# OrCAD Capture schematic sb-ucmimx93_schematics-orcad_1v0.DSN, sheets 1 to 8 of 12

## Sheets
1 01 Index and Block Diagram: title: SB-UCMIMX93   01. INDEX AND BLOCK DIAGRAM; rev: 1.0; note: 8000215000
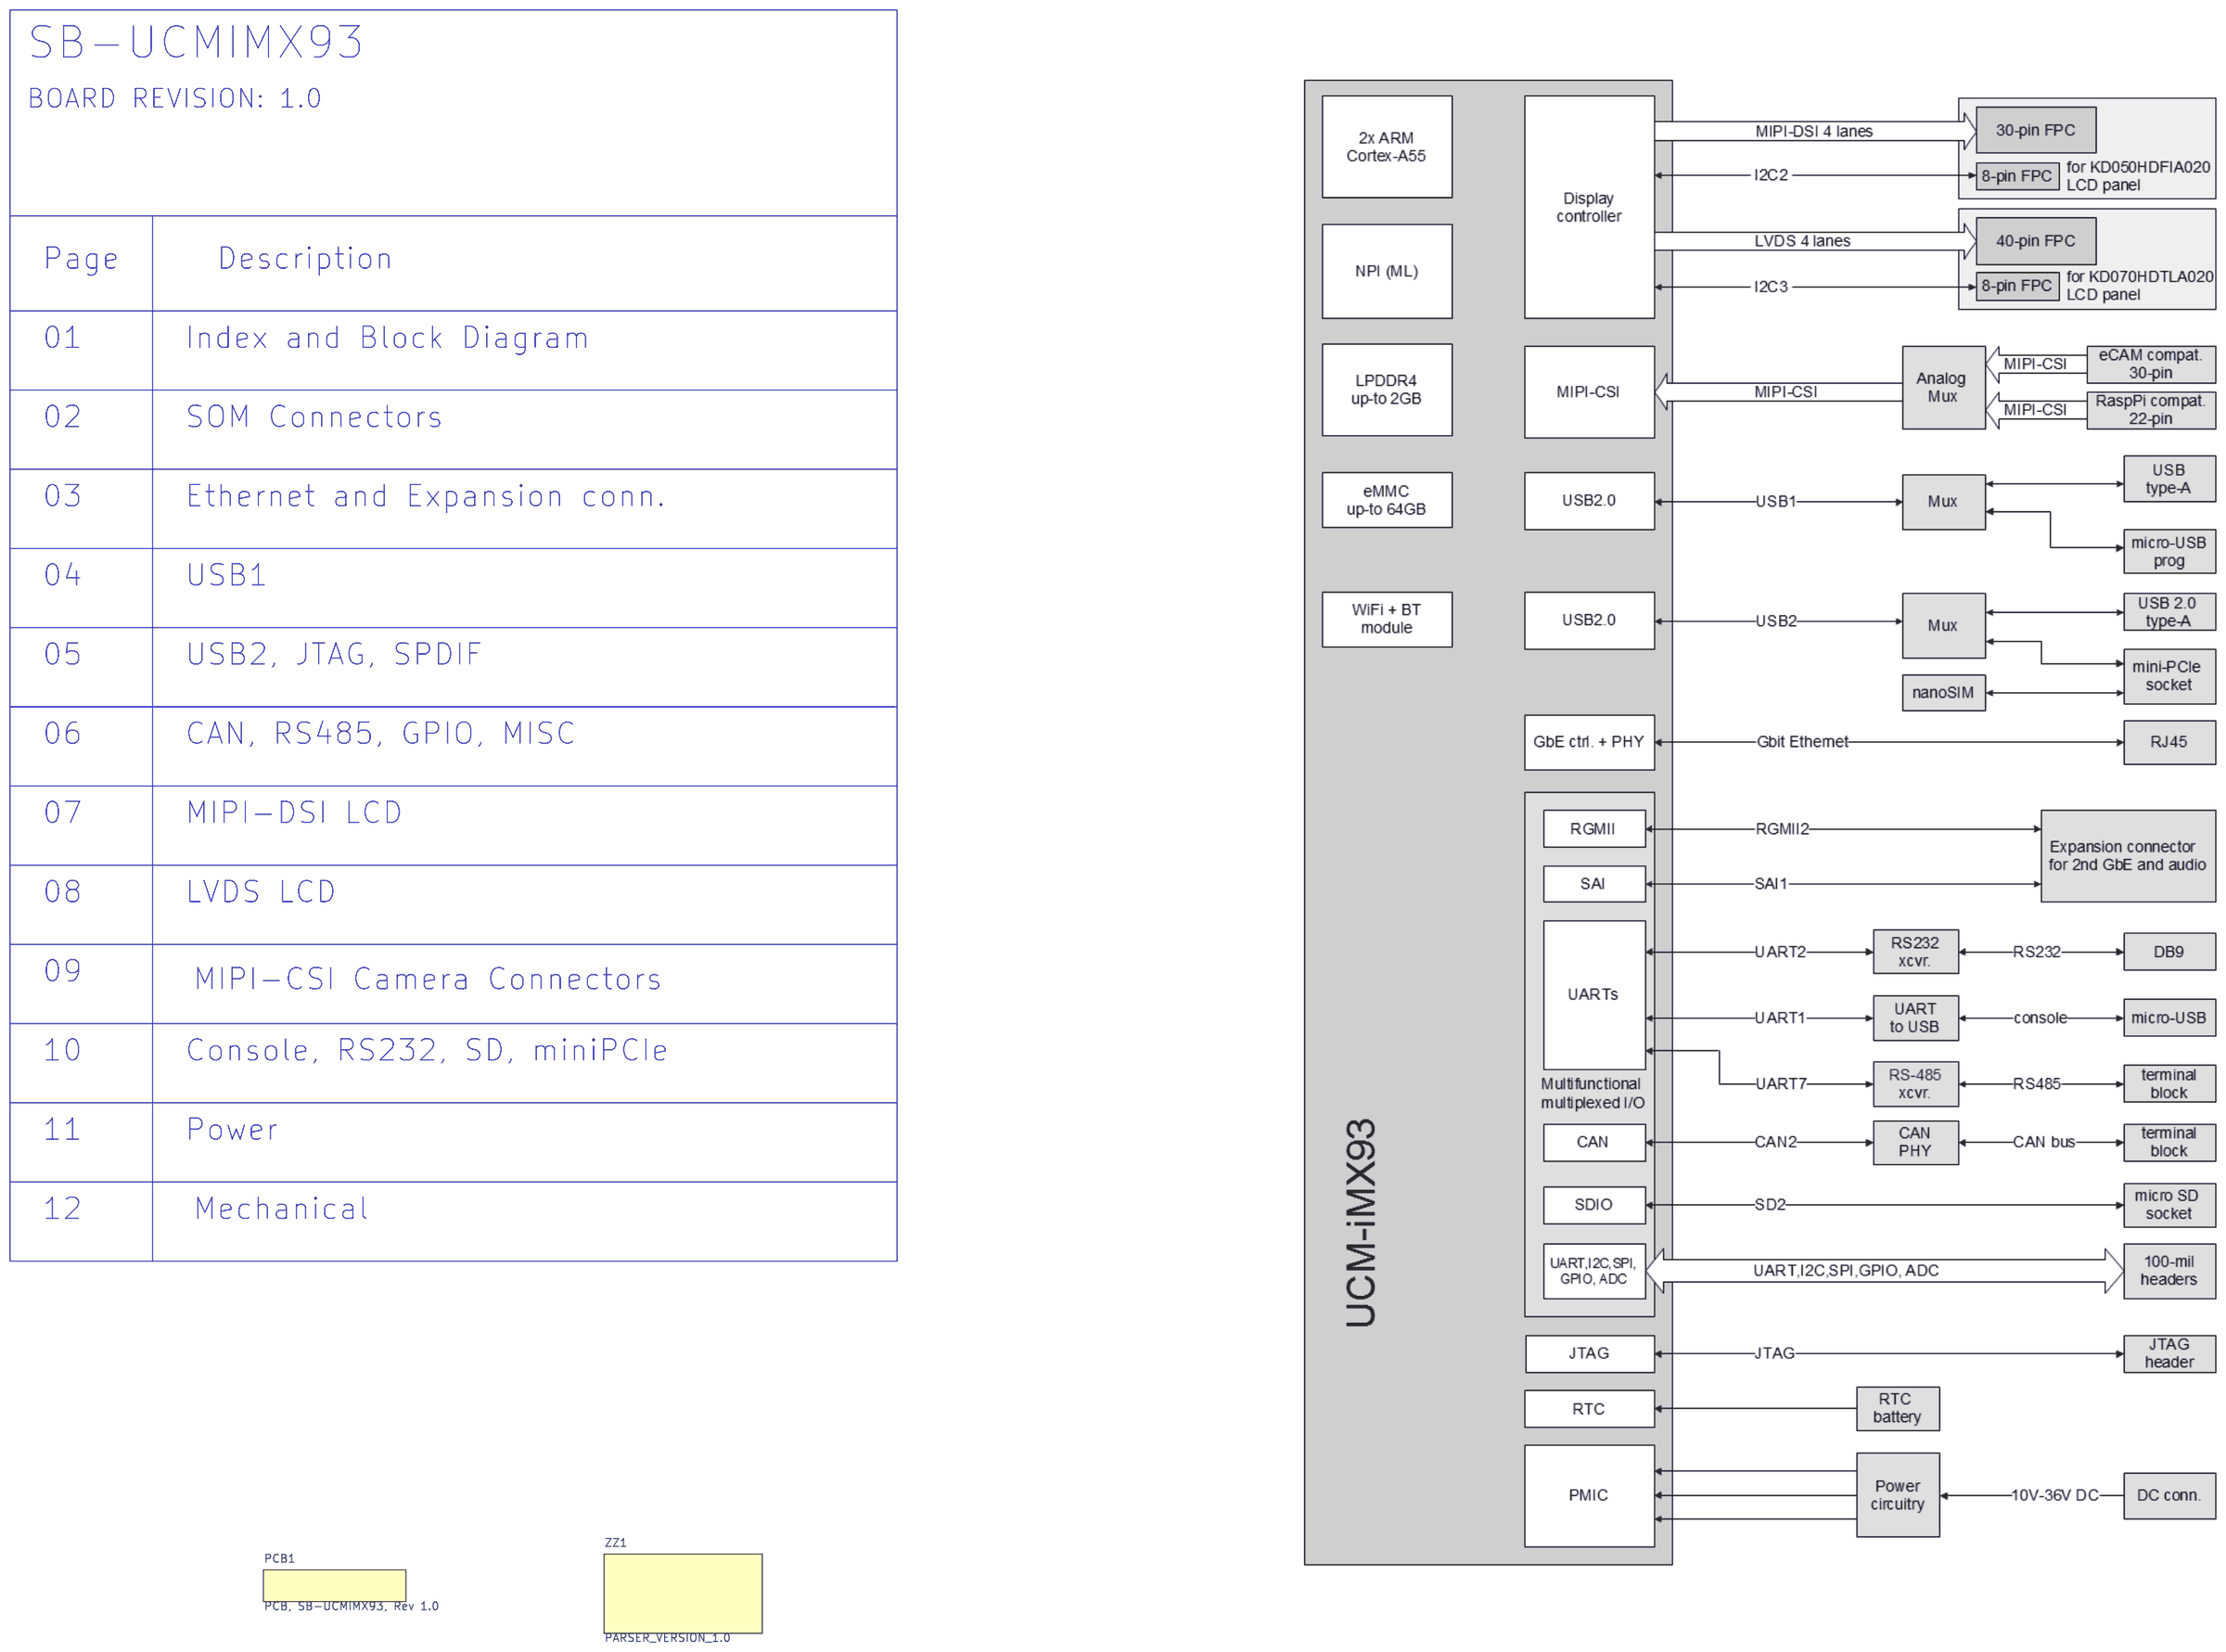
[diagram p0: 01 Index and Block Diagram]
2 05 USB2, JTAG, SPDIF: size A3; title: SB-UCMIMX93      05. USB2, JTAG, SPDIF
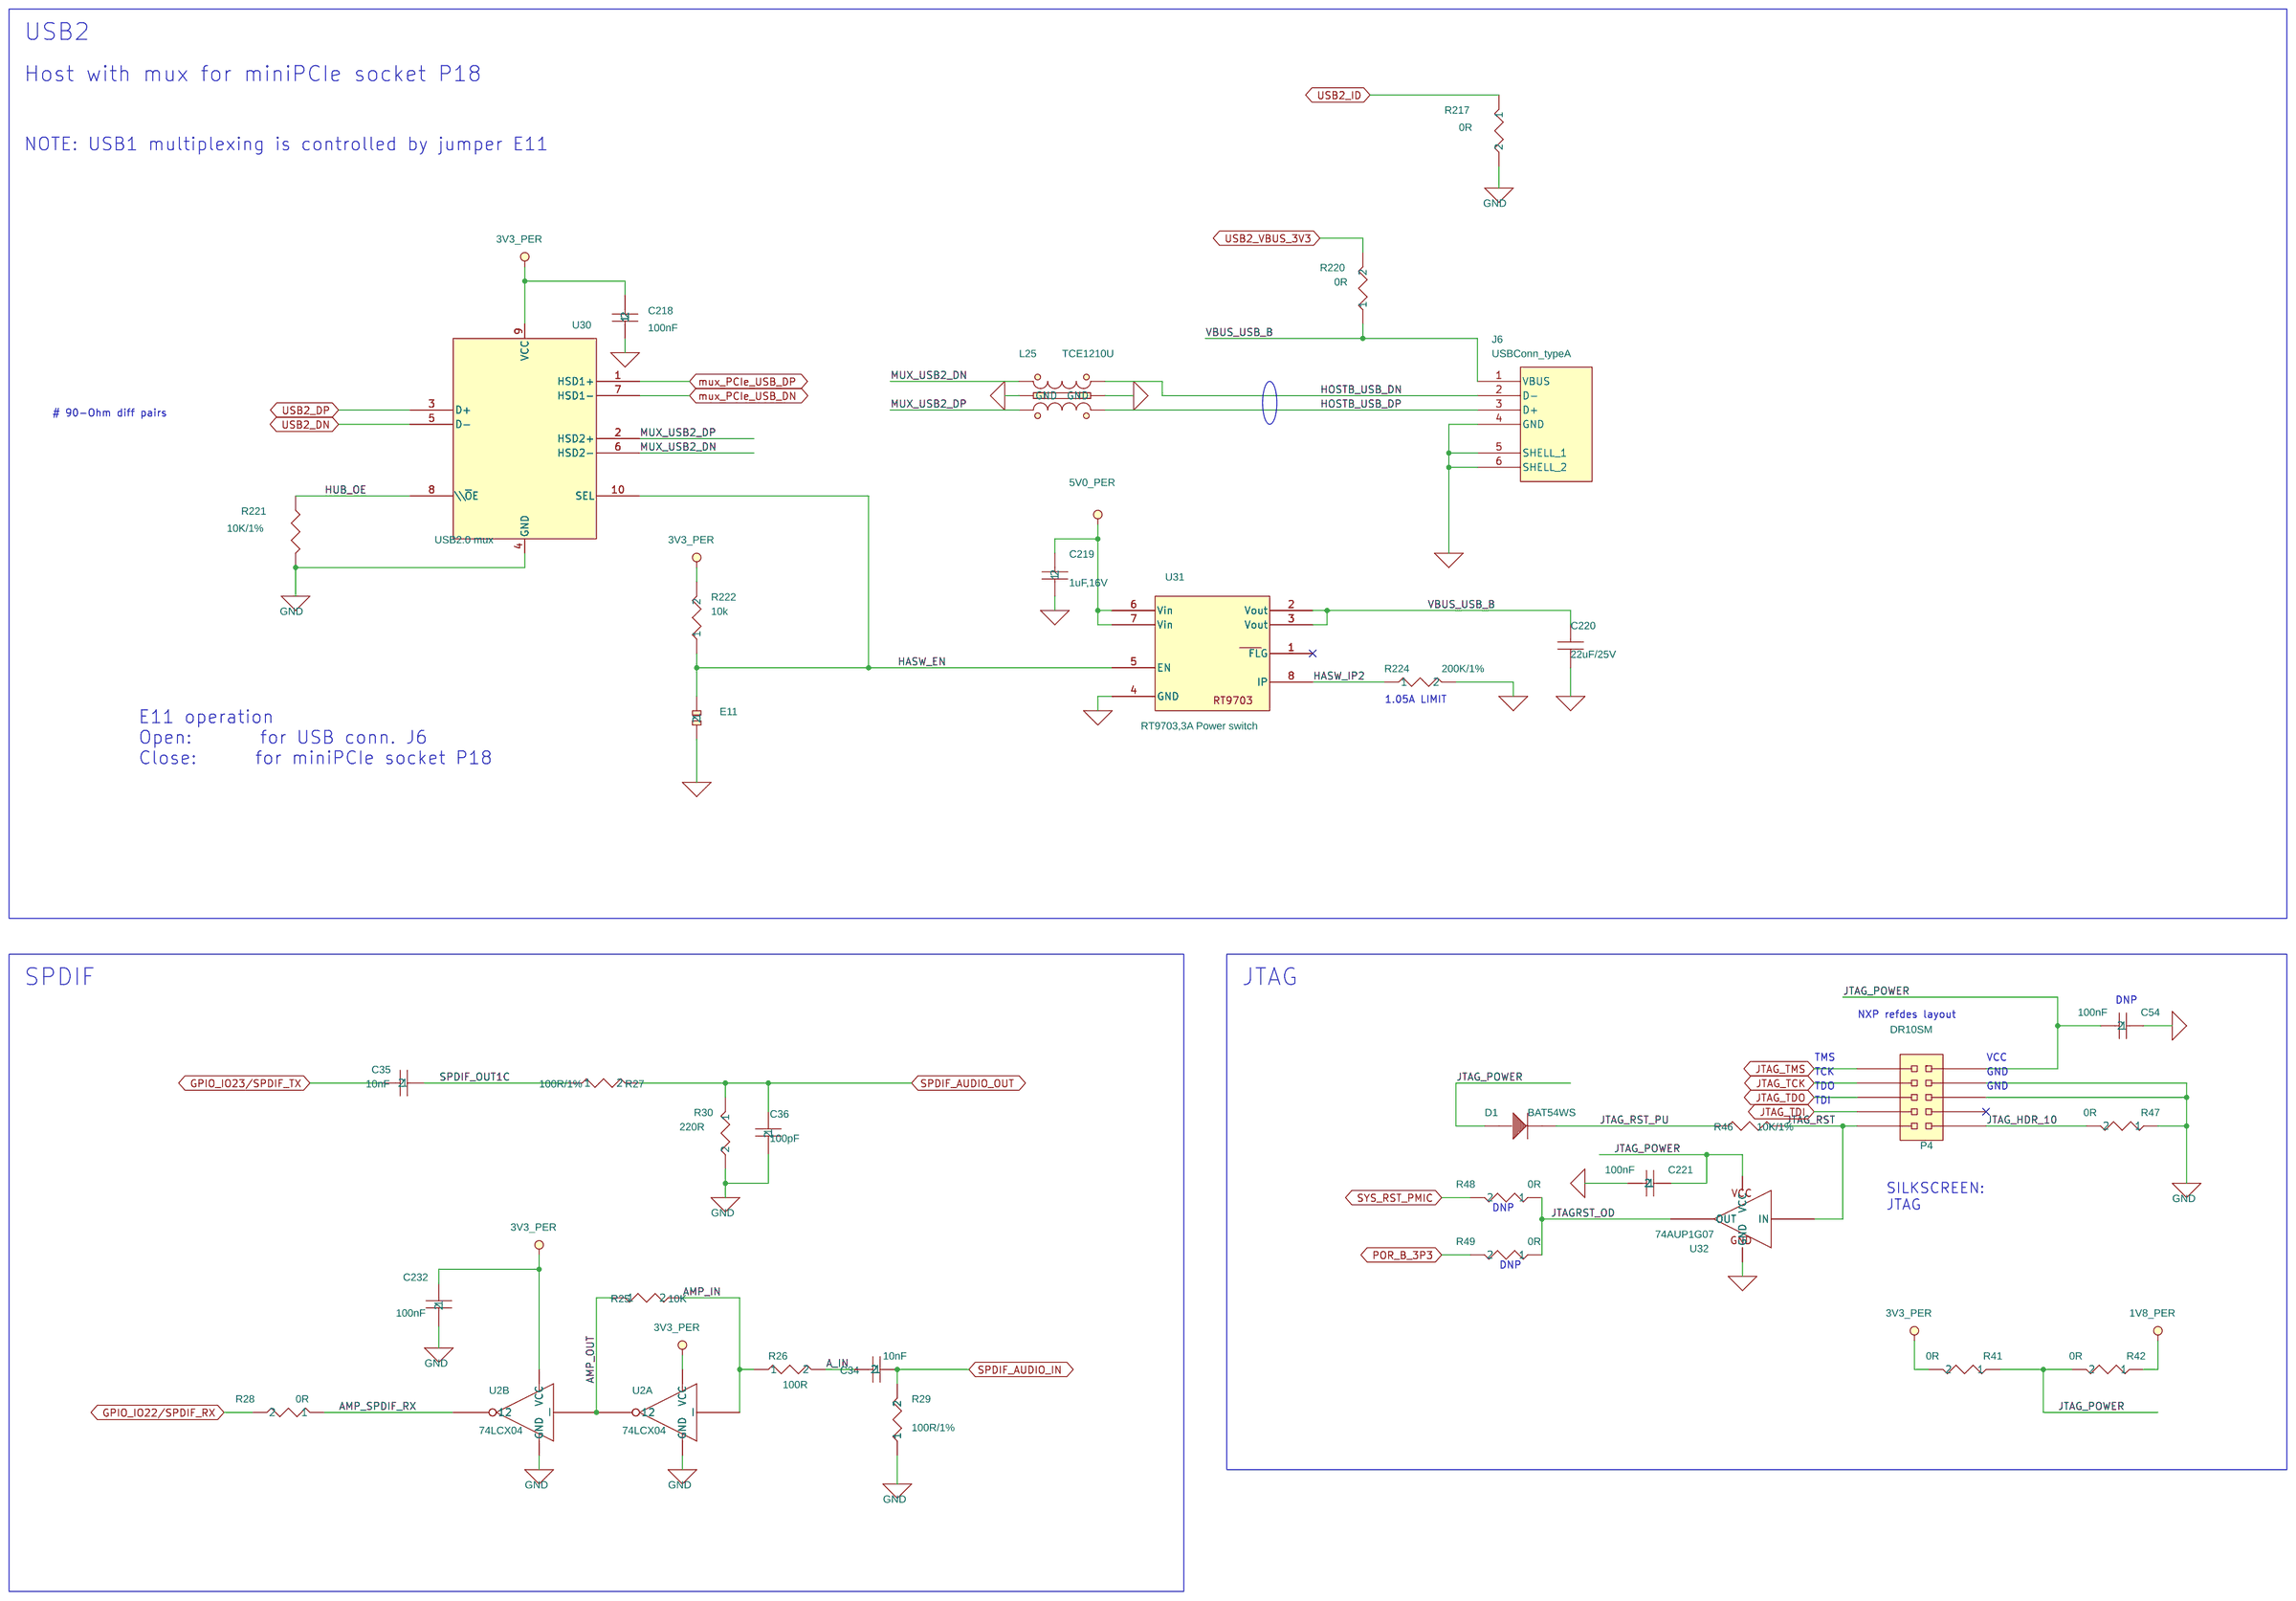
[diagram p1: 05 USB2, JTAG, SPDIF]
3 02 SOM Connectors: size A3; title: SB-UCMIMX93   02. SOM CONNECTORS; note: 17 HaYetsira Street; note: Yokneam Illit, Israel 2069208
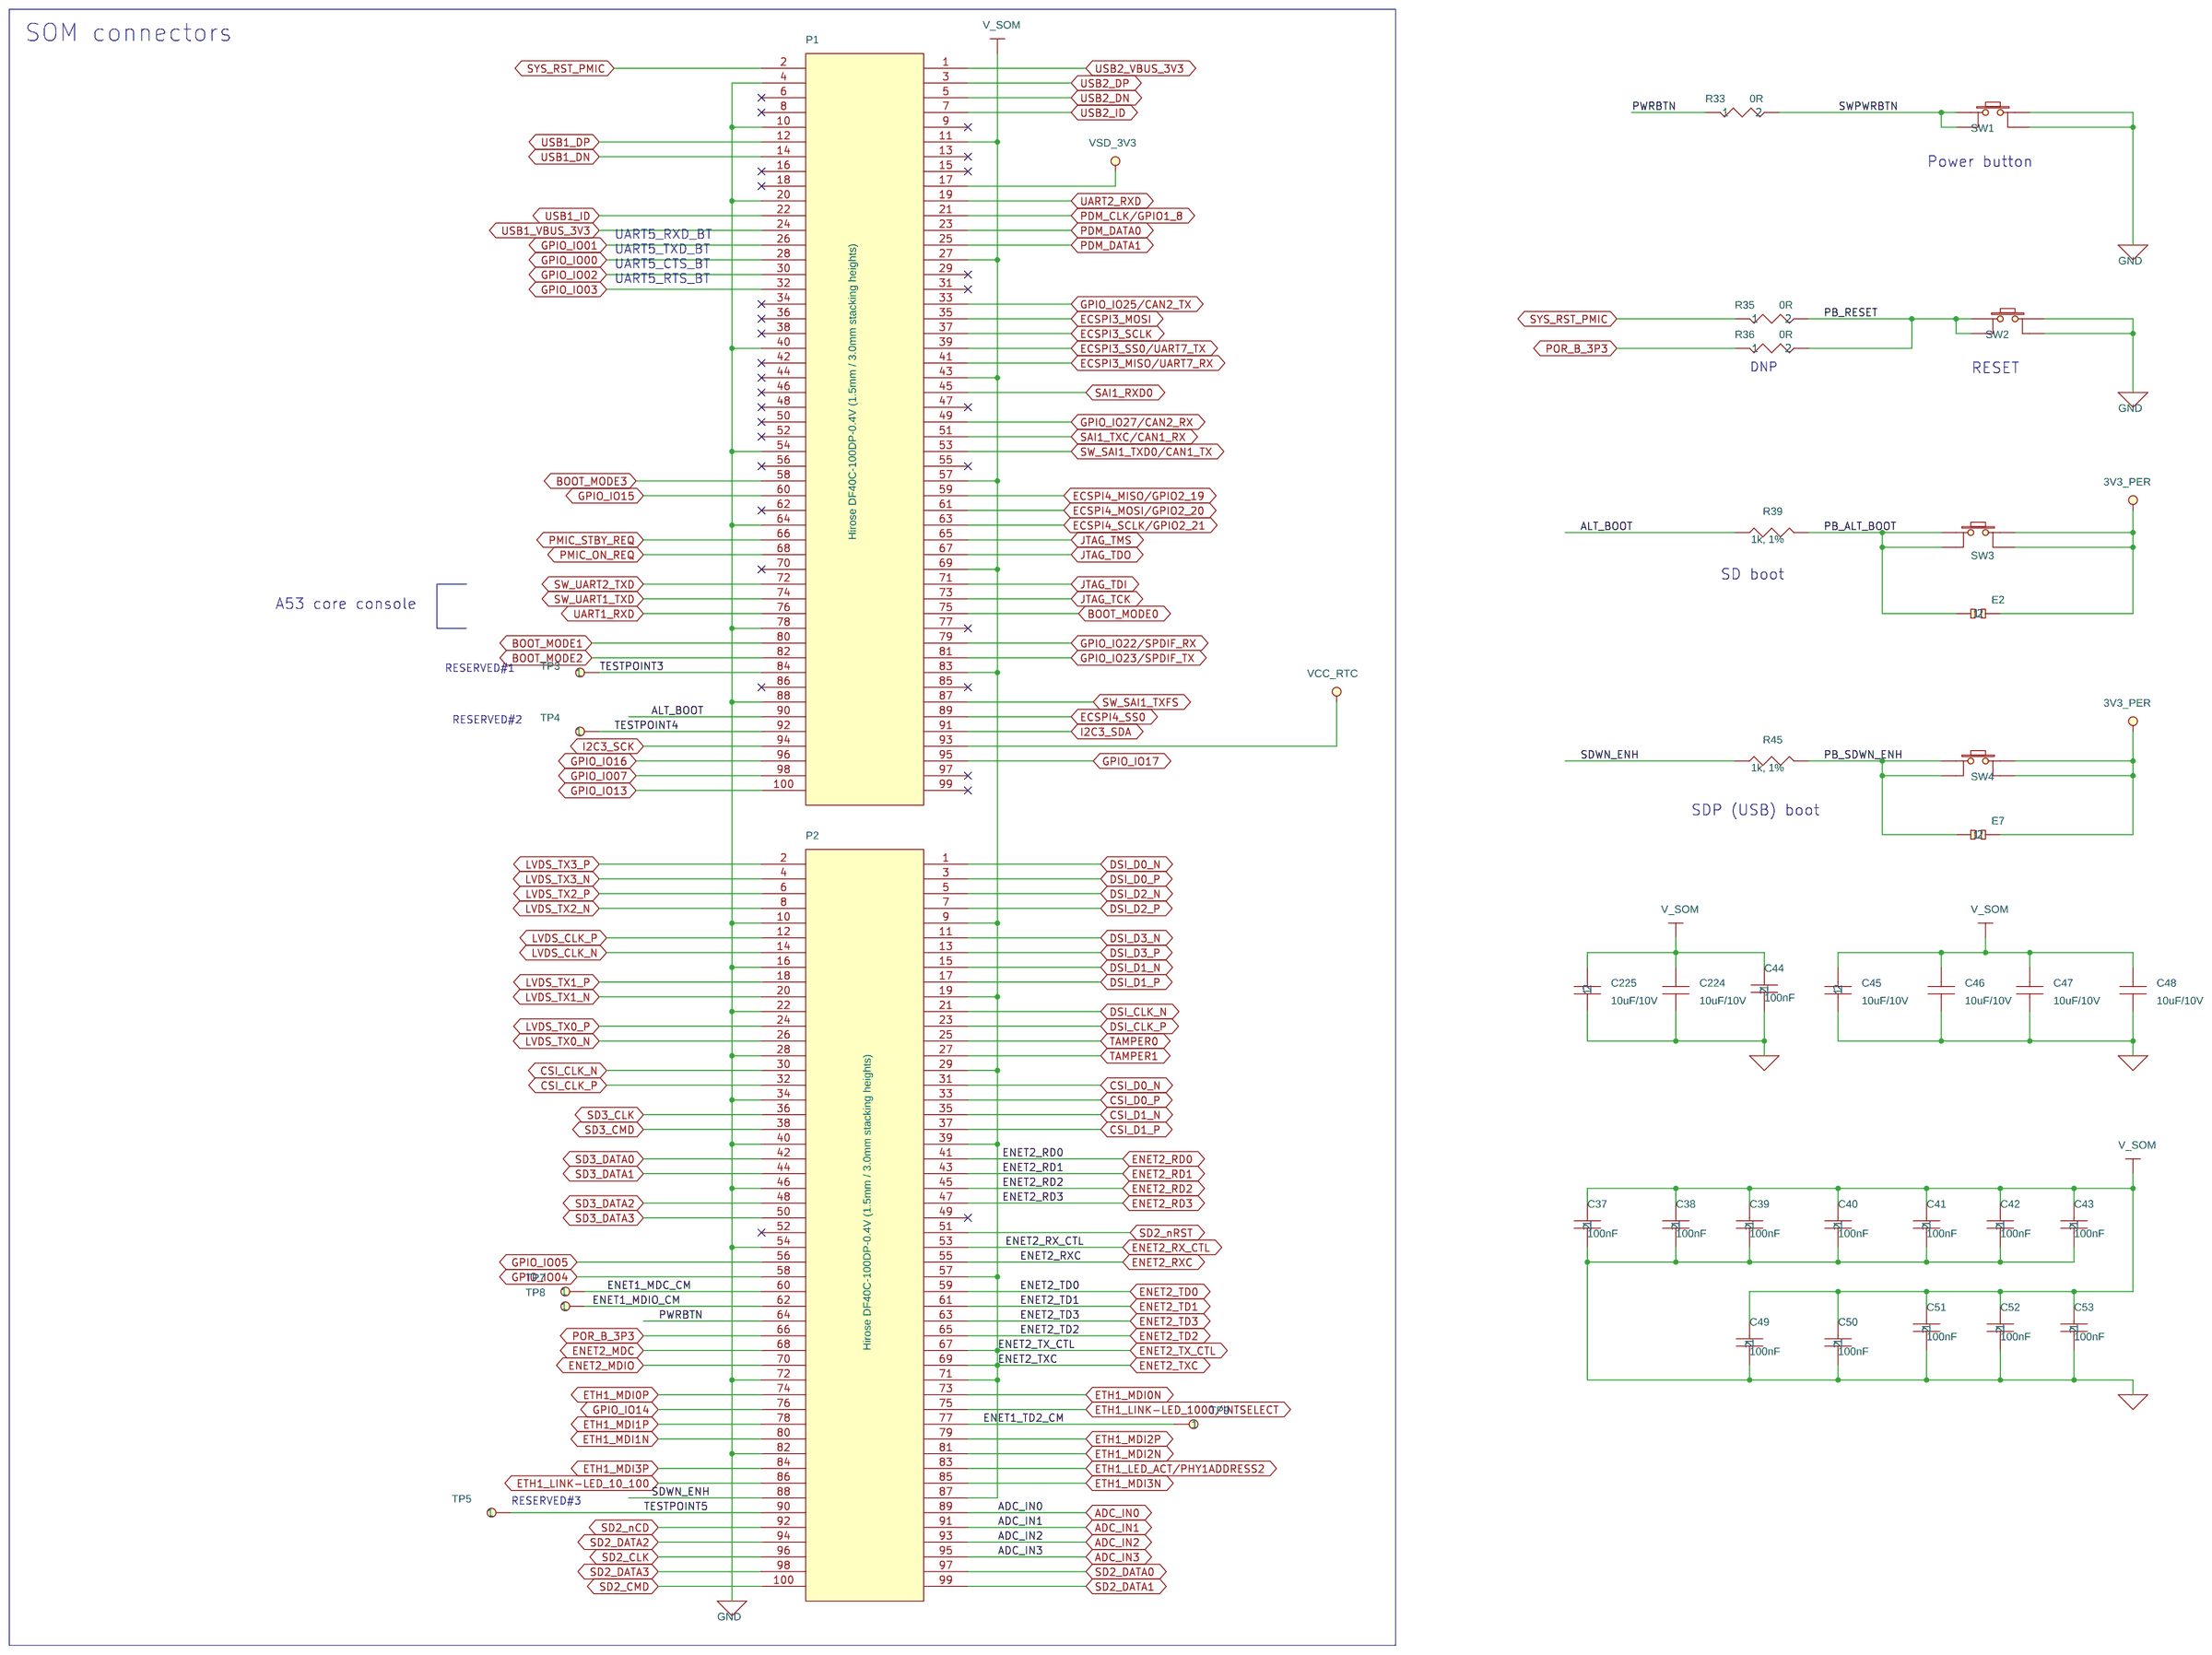
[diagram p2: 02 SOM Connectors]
4 06 CAN, RS485, GPIO, MISC: size A3; title: SB-SOM-iMX8PLUS    06. JTAG, CAN, GPIO Exp., Misc.; note: 8000103001
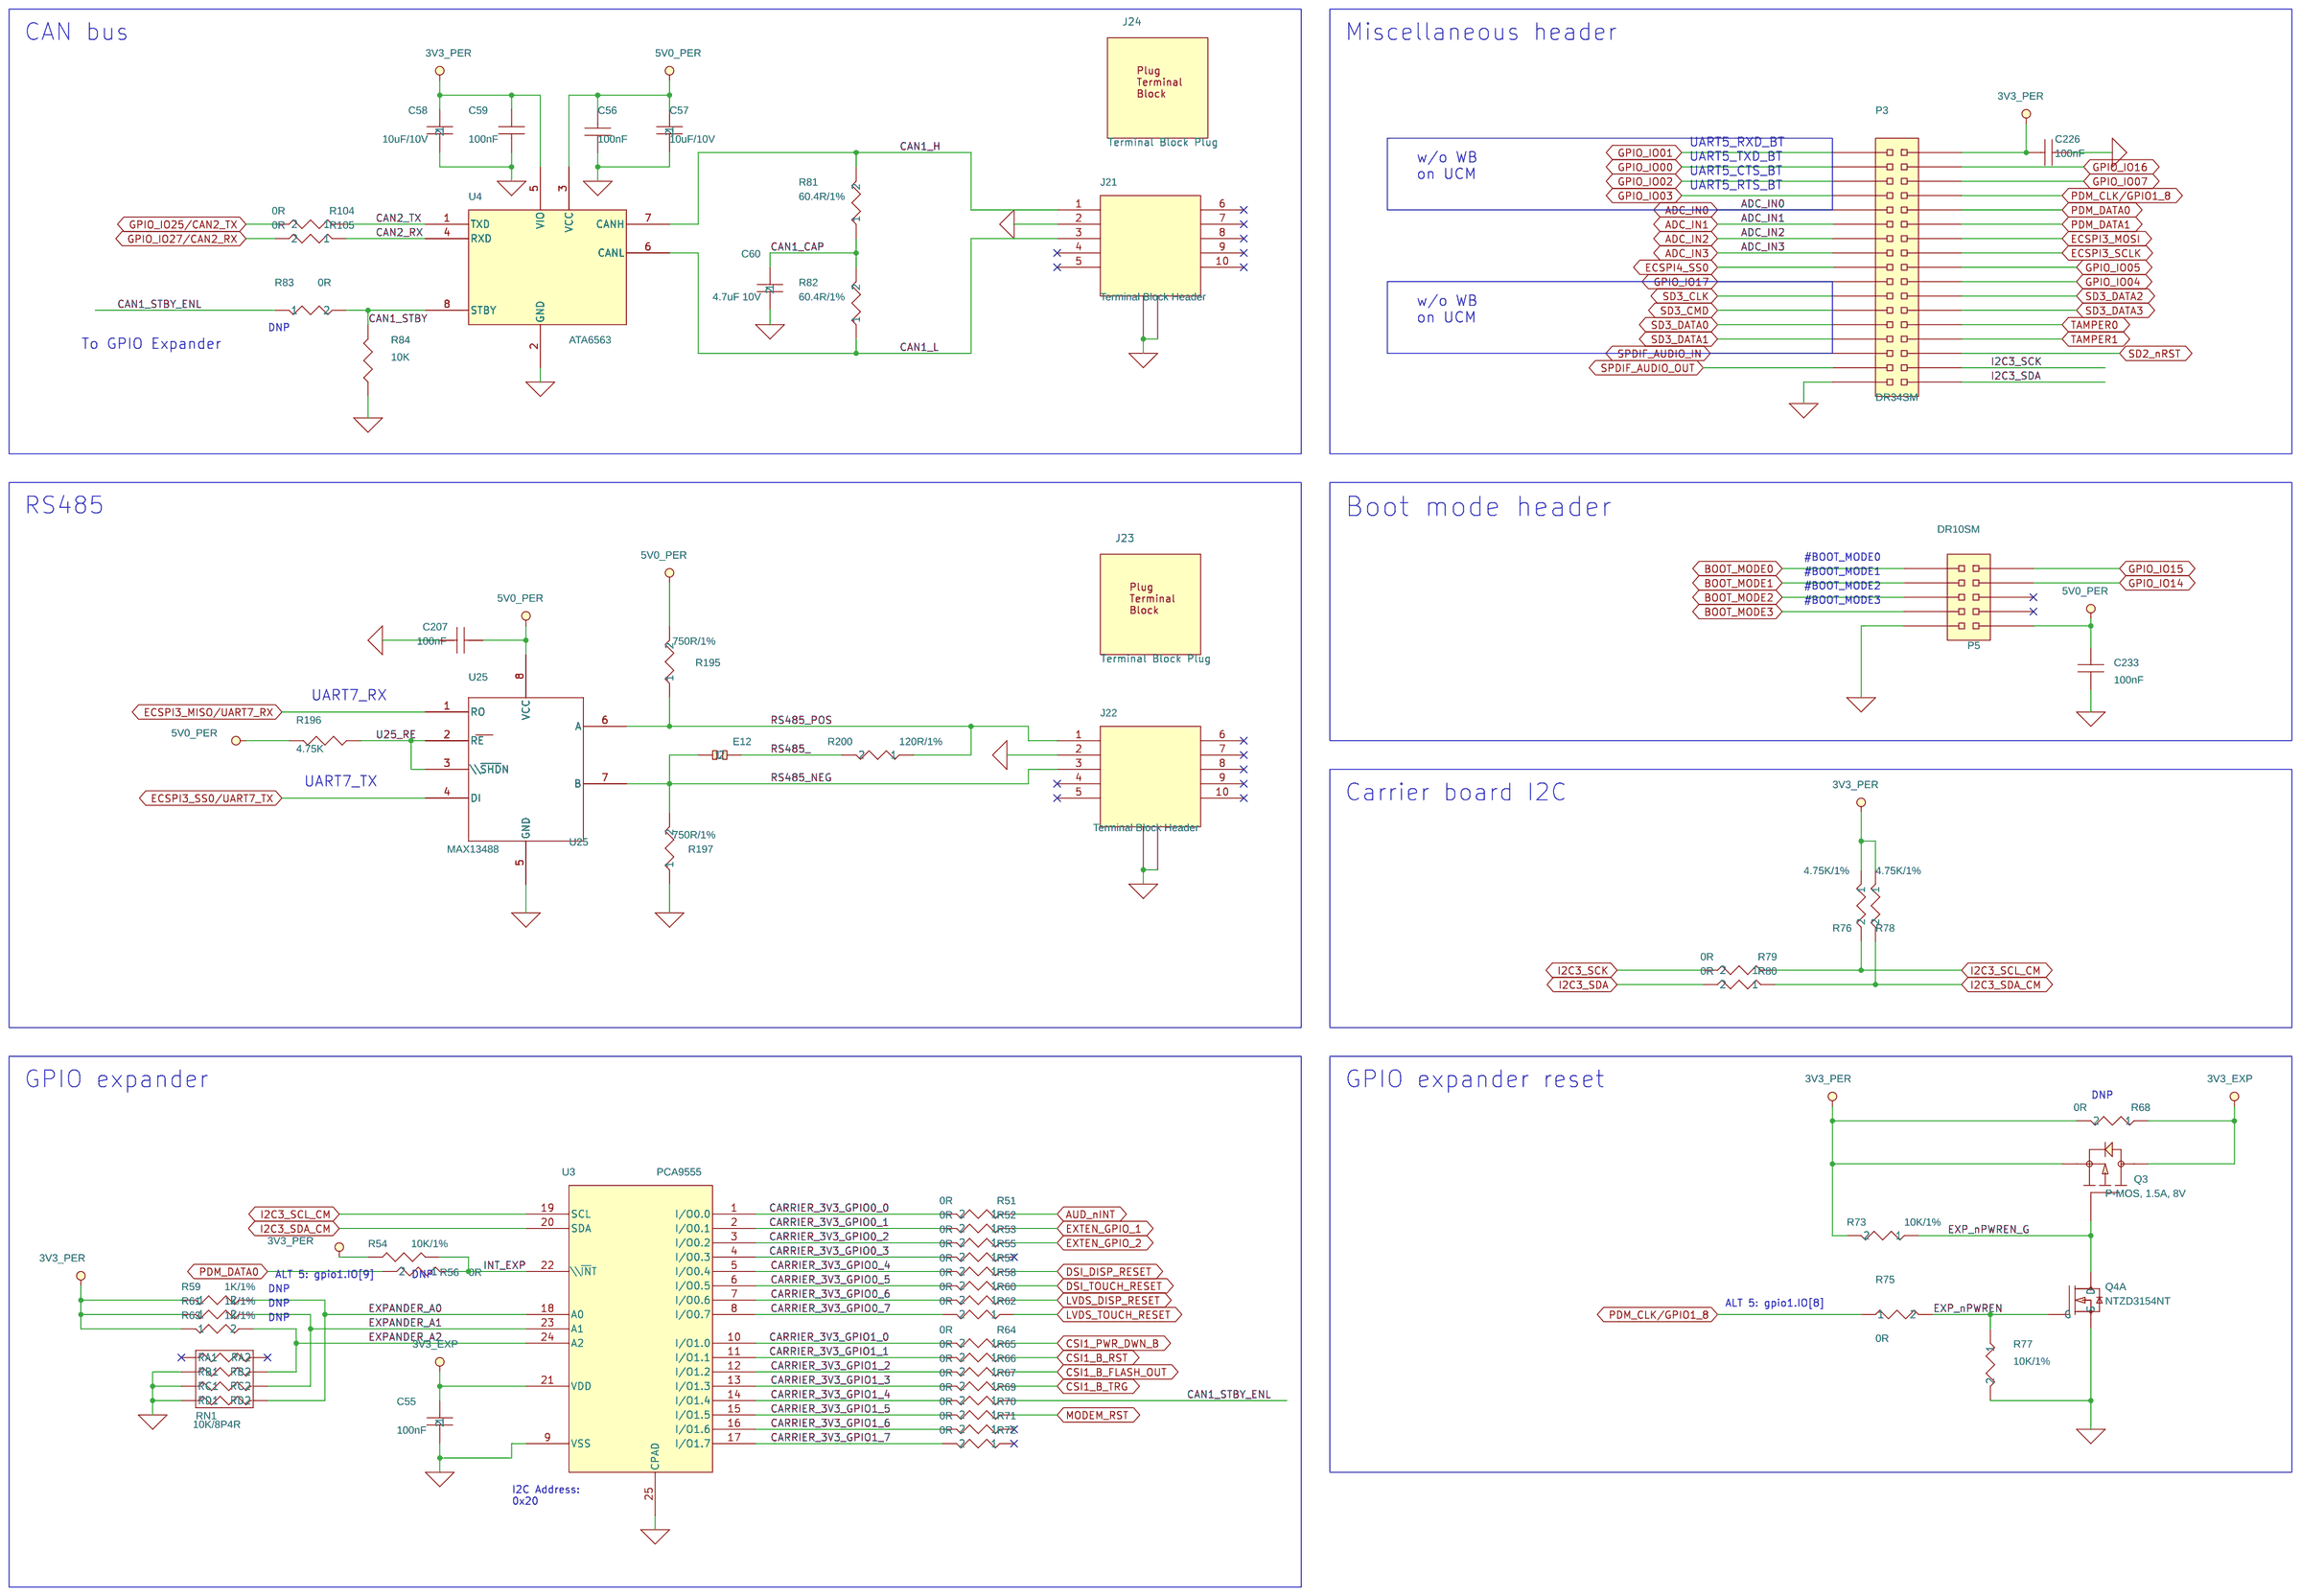
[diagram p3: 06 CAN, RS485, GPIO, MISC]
5 08 LVDS LCD: size A3; title: SB-UCMIMX93   08. LVDS LCD
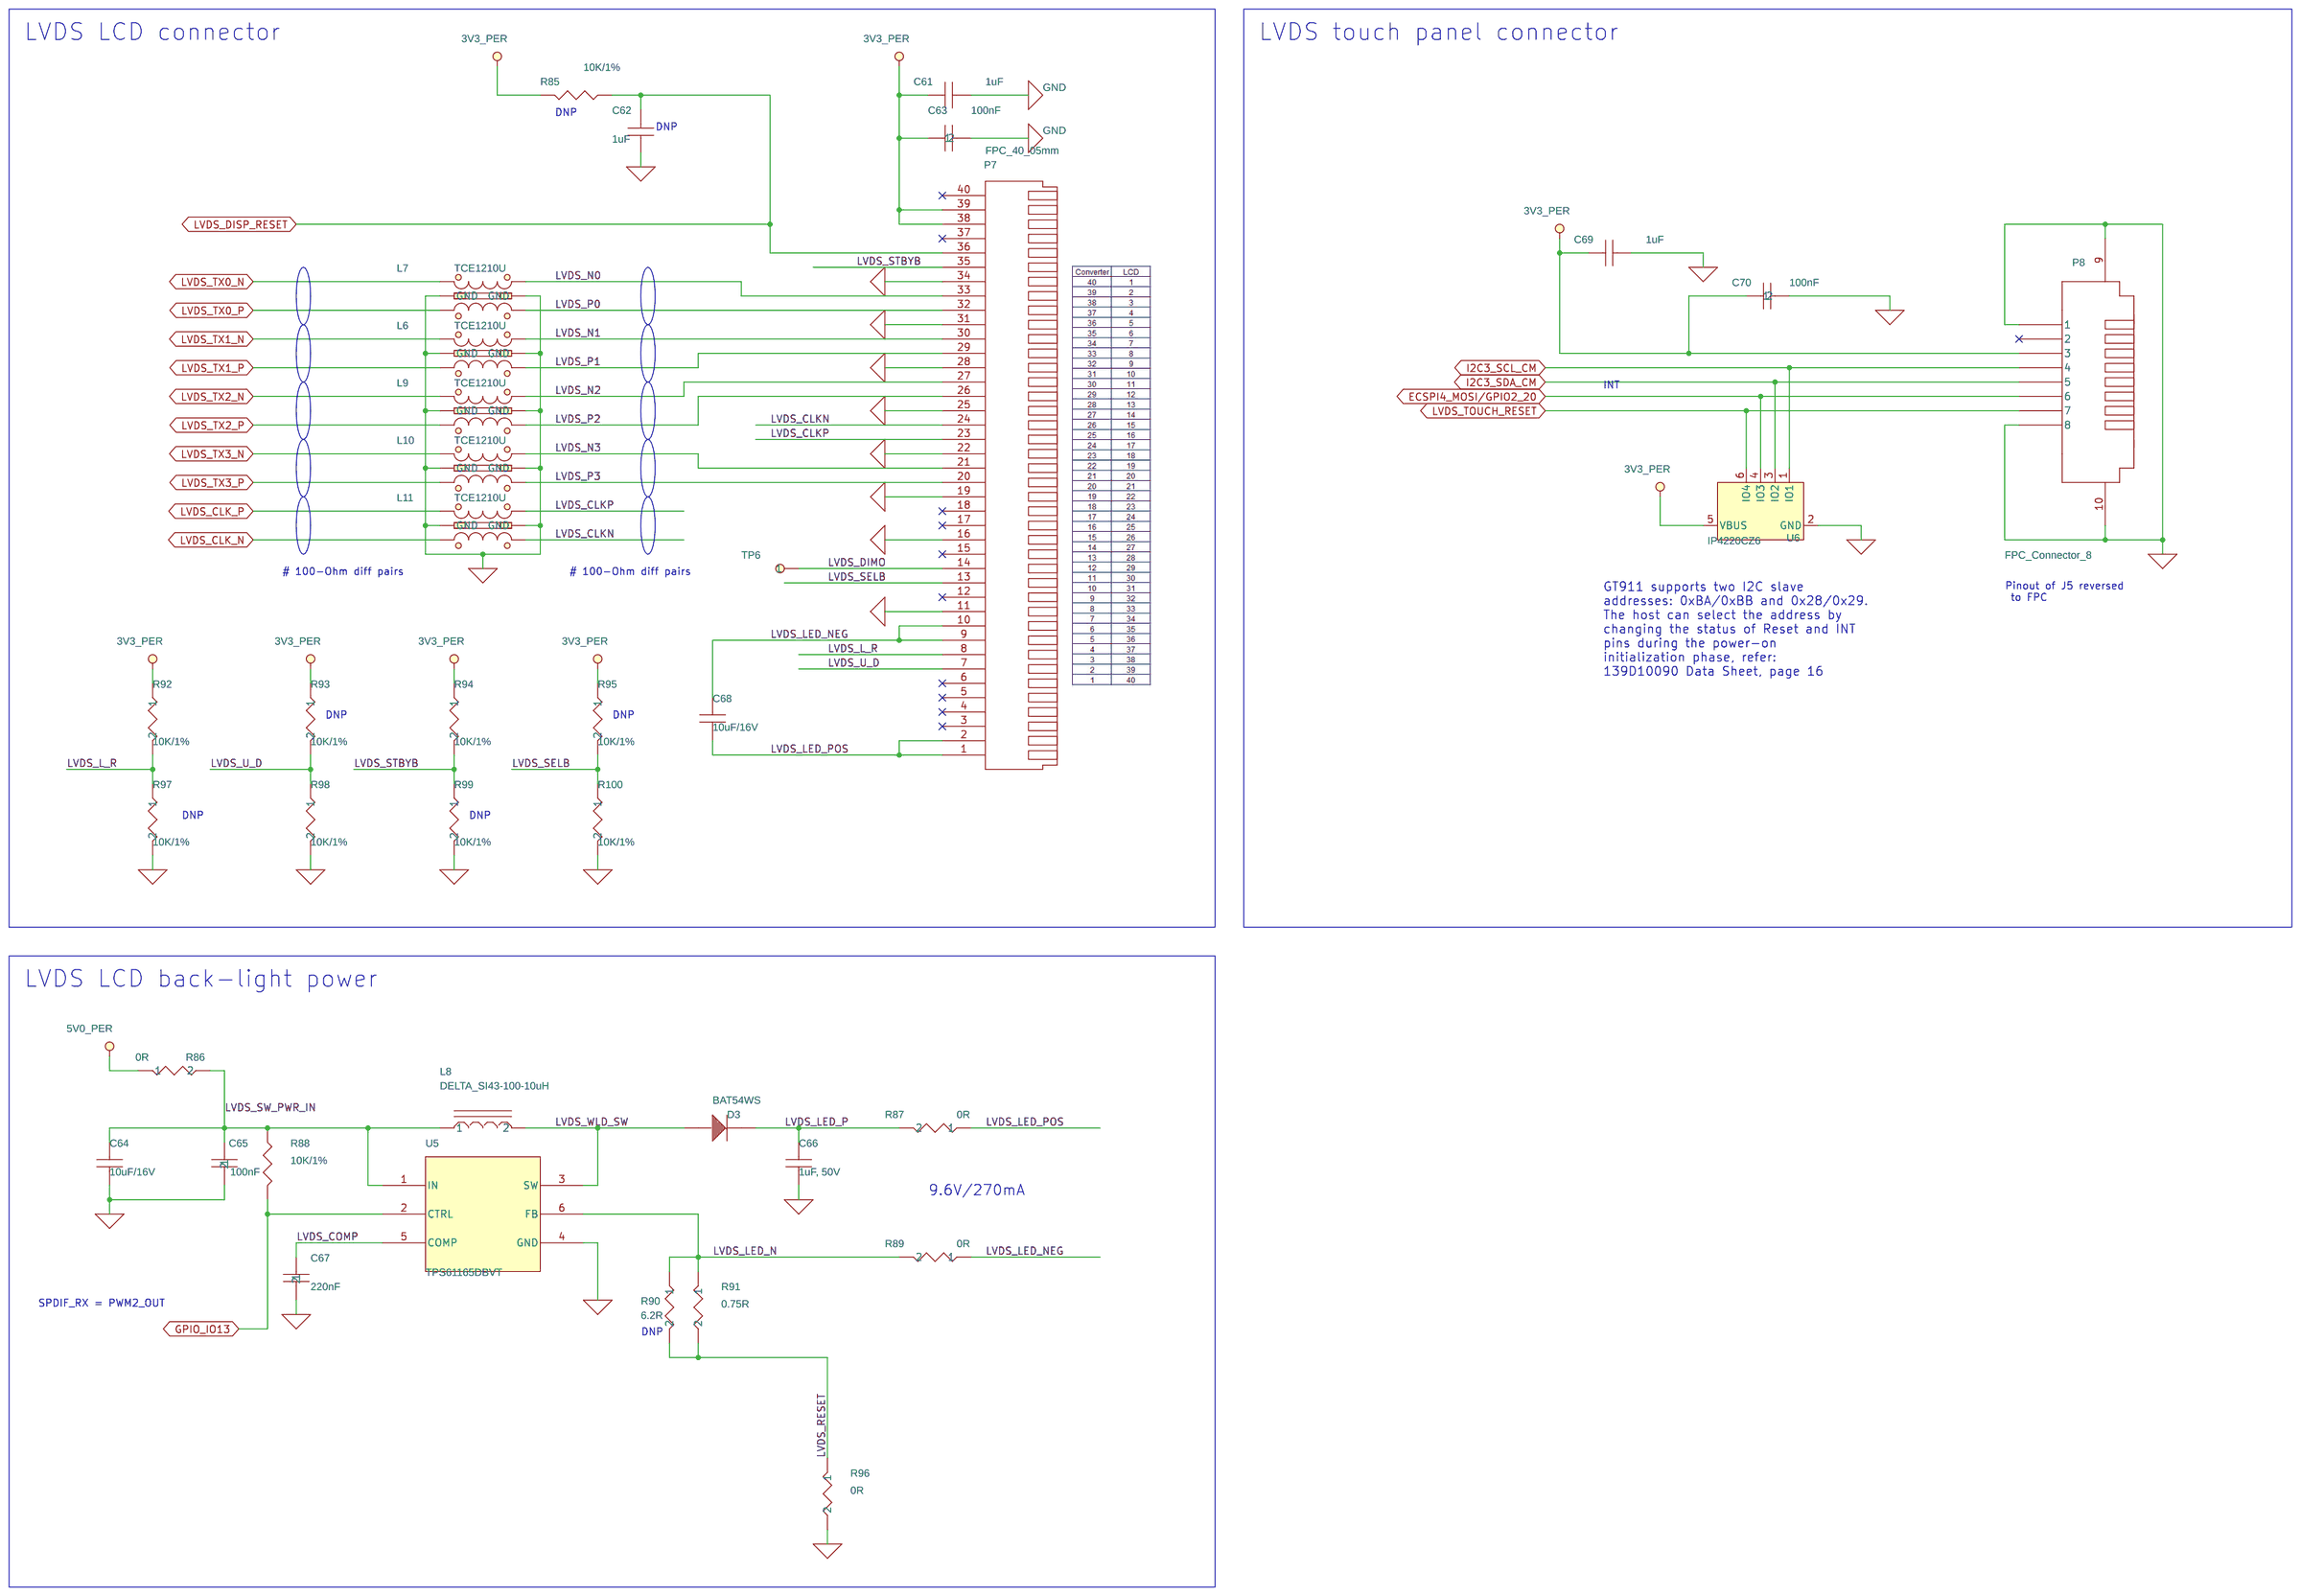
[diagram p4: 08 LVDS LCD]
6 12 Mechanical: size A3; title: SB-UCMIMX93      12. Mechanical
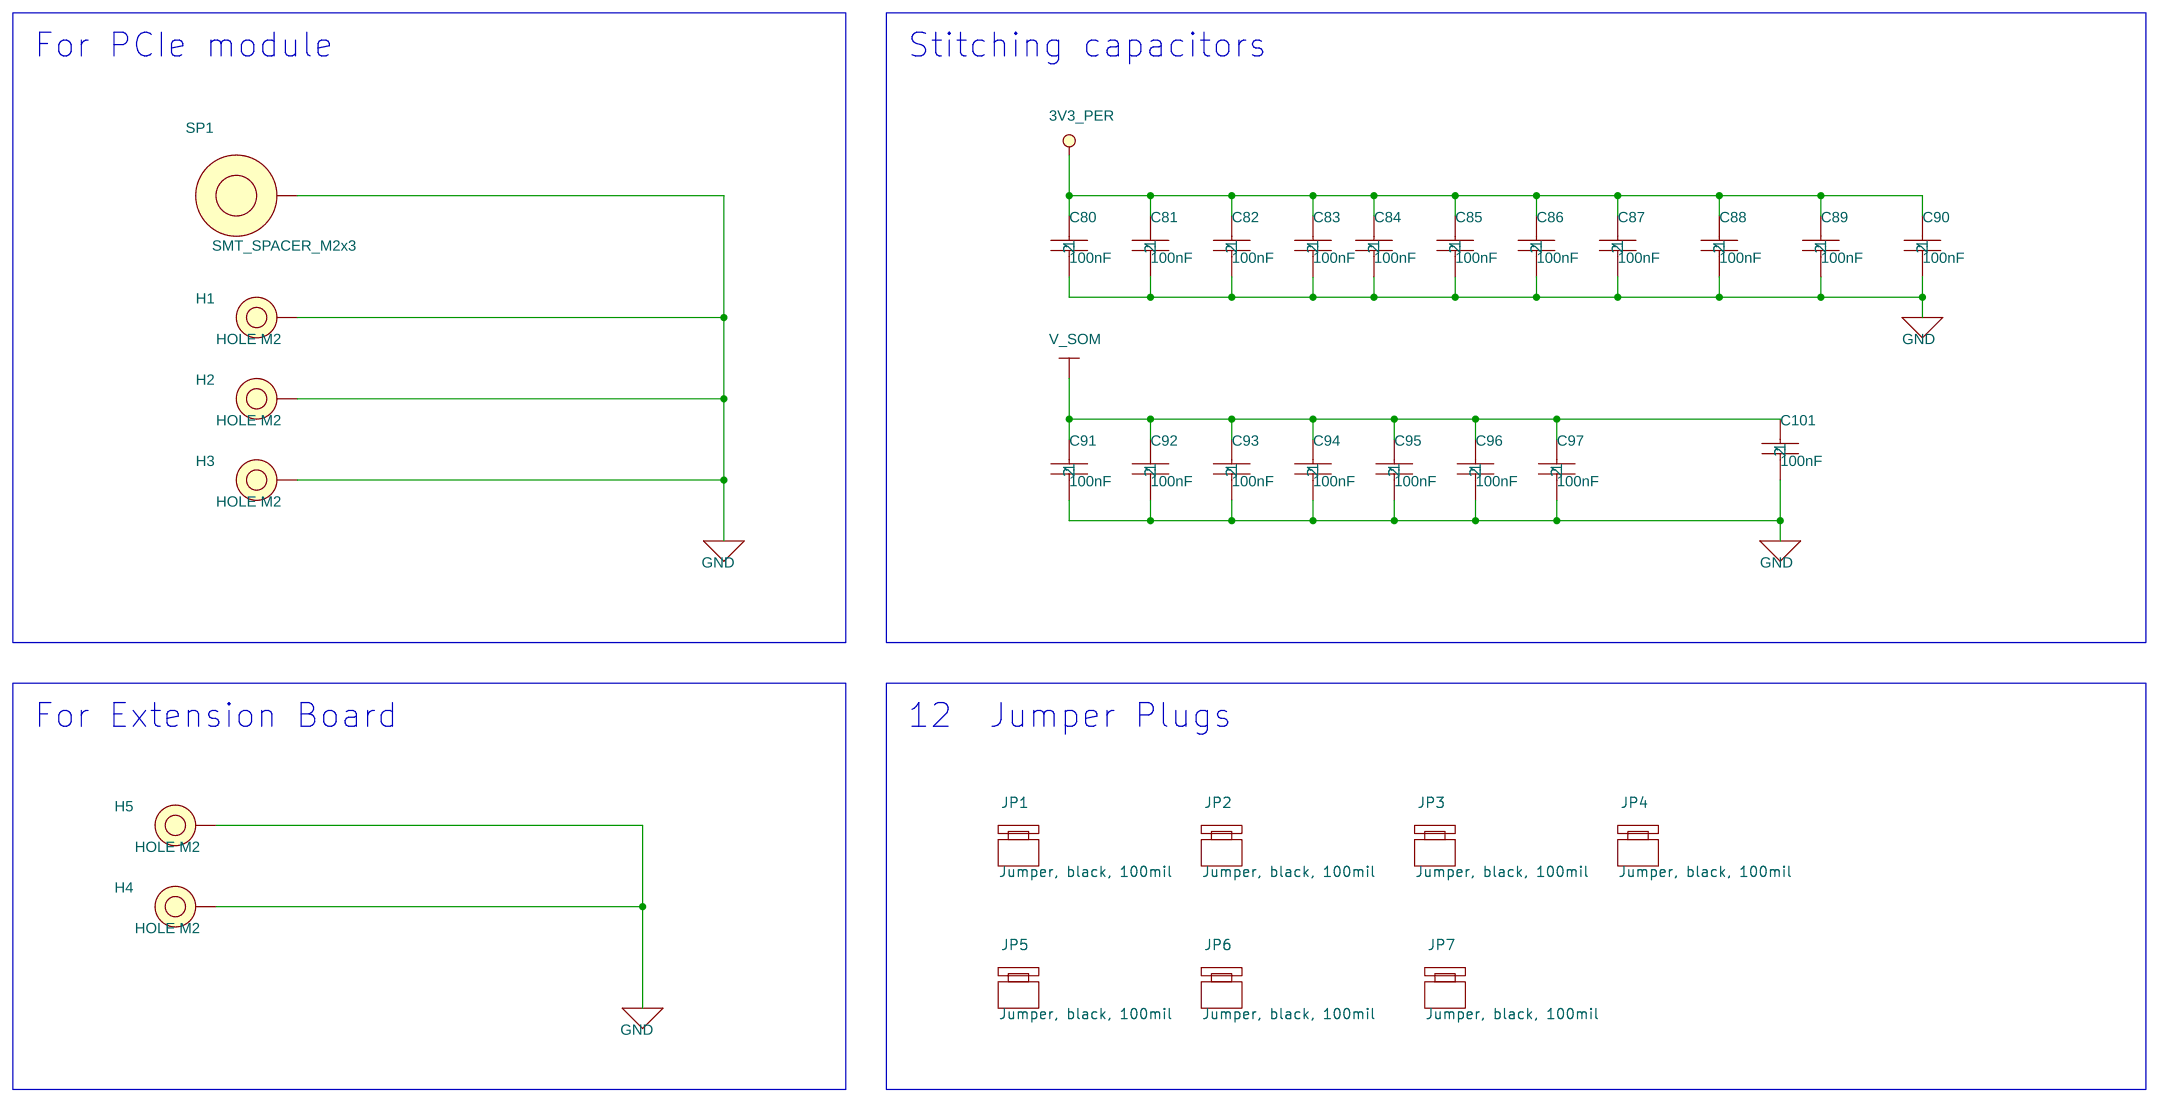
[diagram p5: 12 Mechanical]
7 09 MIPI-CSI Camera Connectors: size A3; title: SB-UCMIMX93    10. MIPI-CSI Connectors
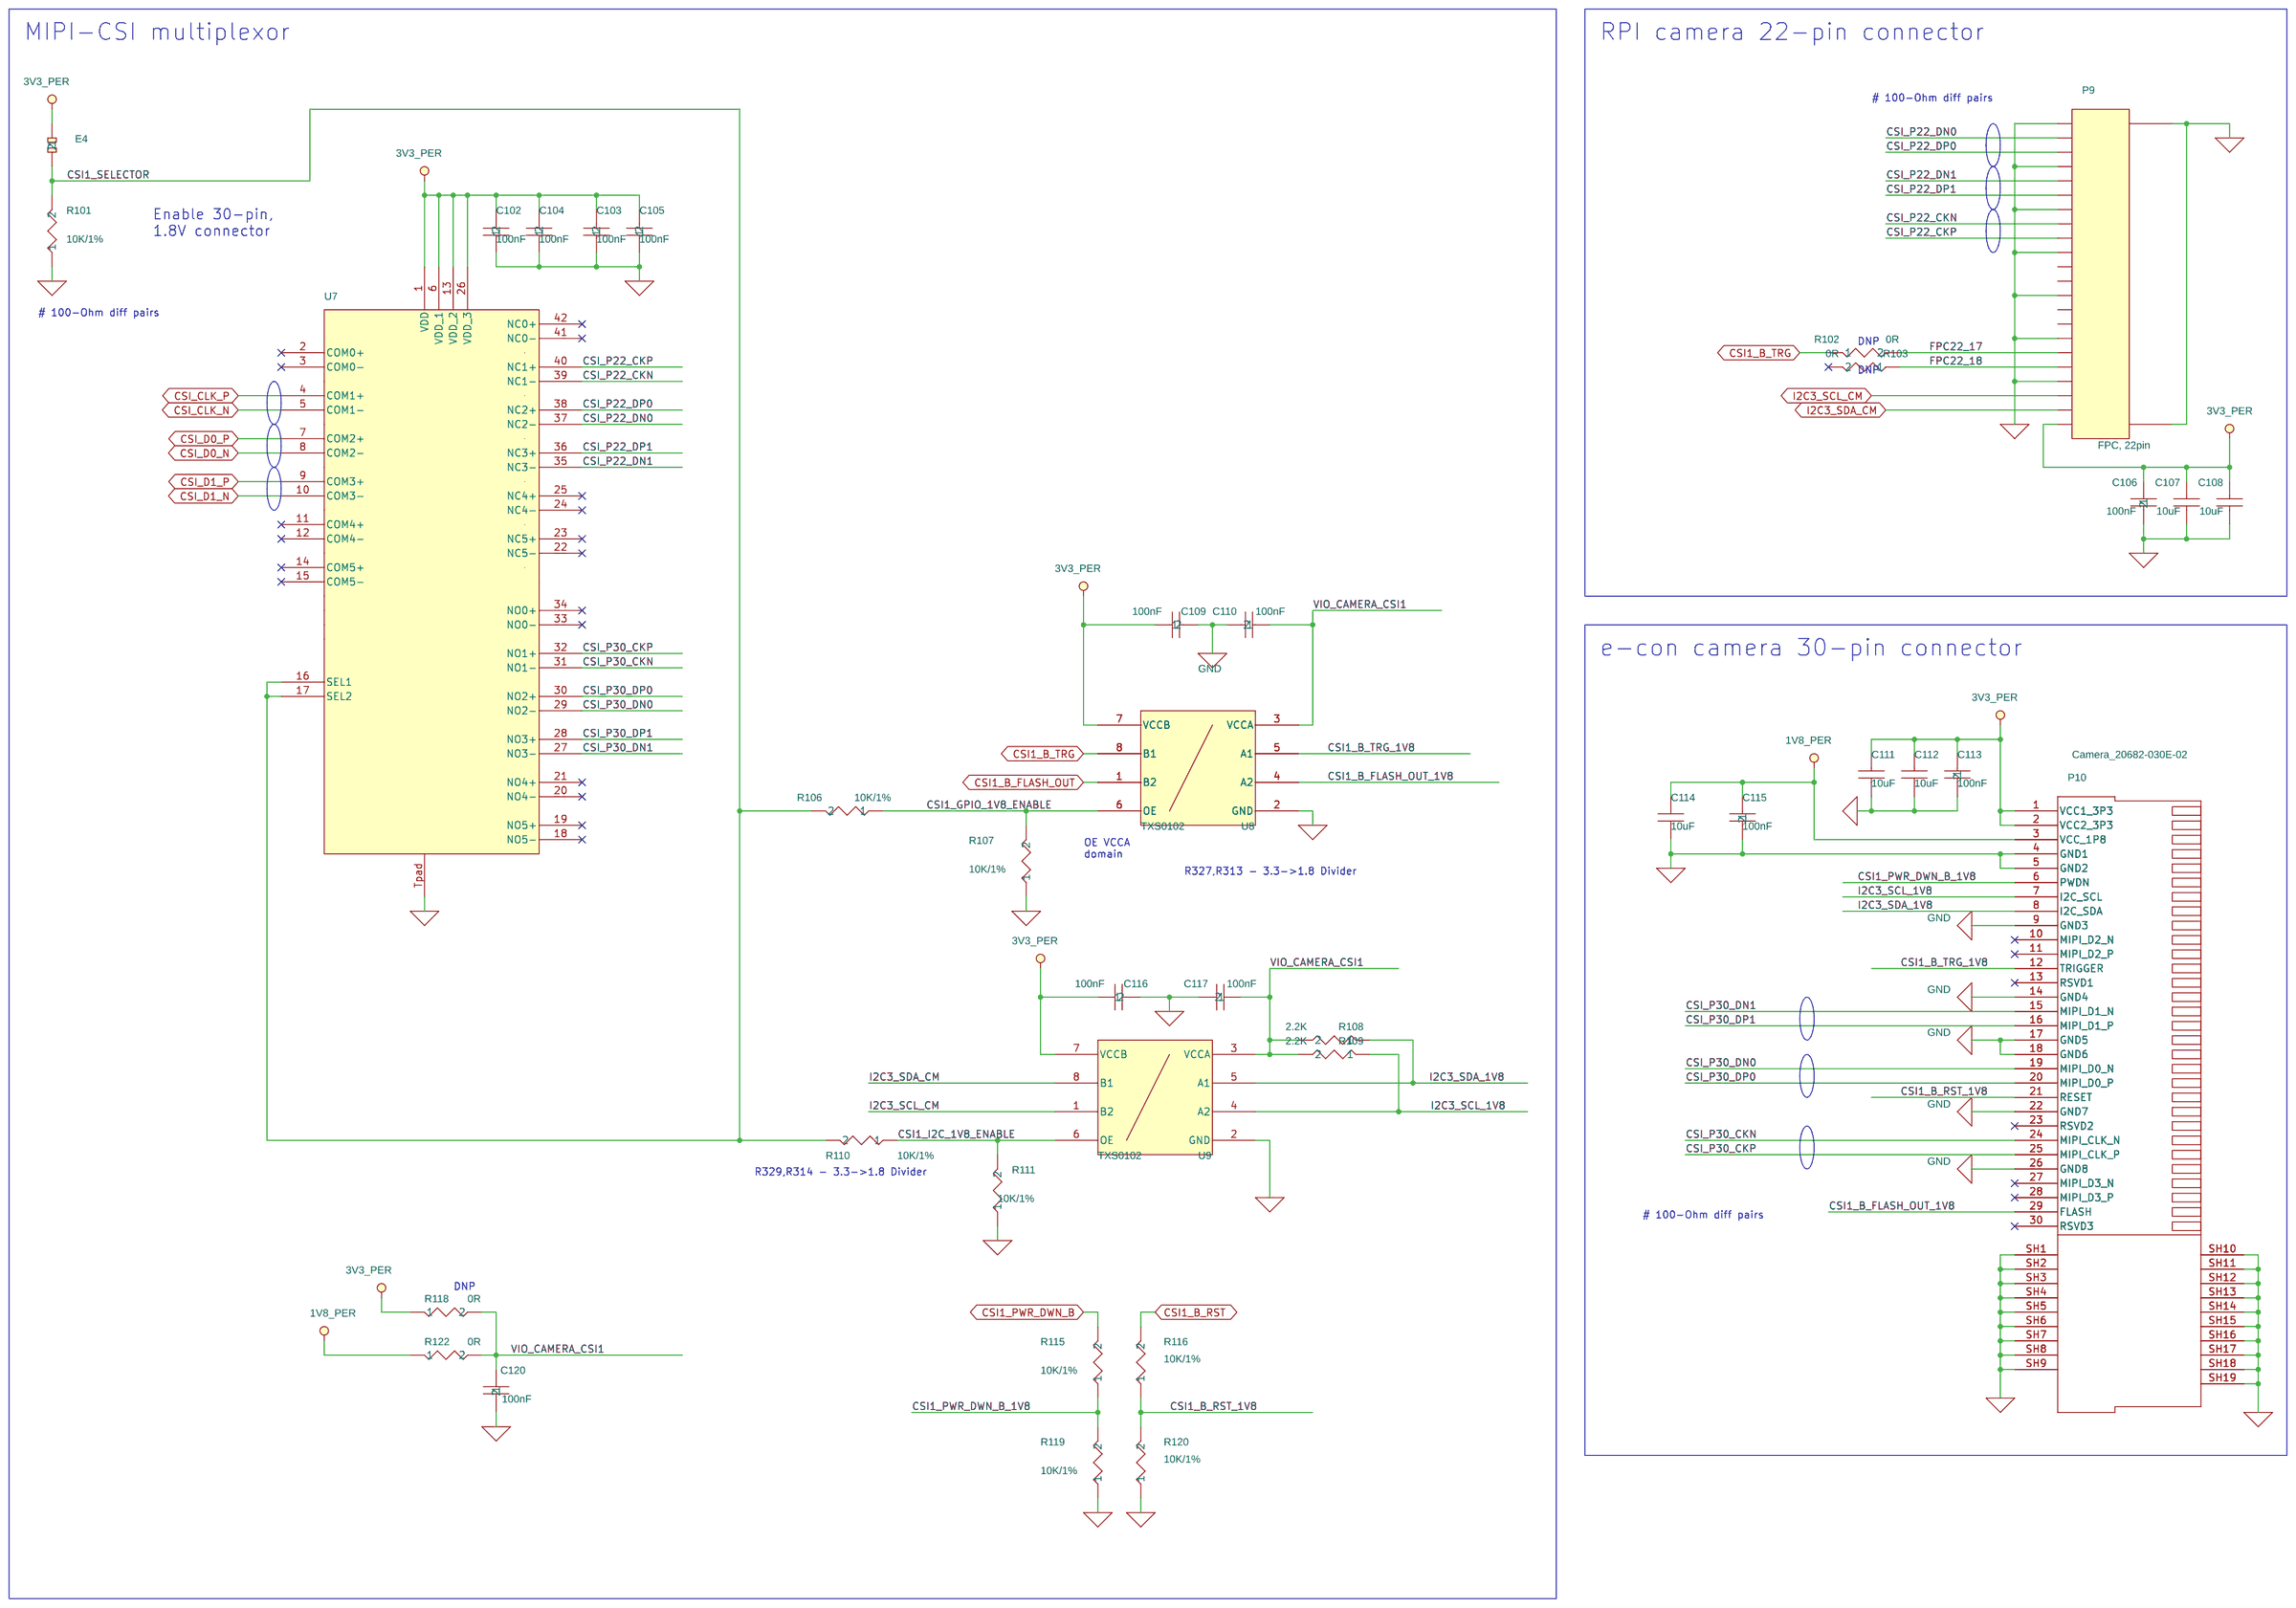
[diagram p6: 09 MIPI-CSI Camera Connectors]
8 07 MIPI-DSI LCD: size A3; title: SB-UCMIMX93   07. MIPI-DSI LCD
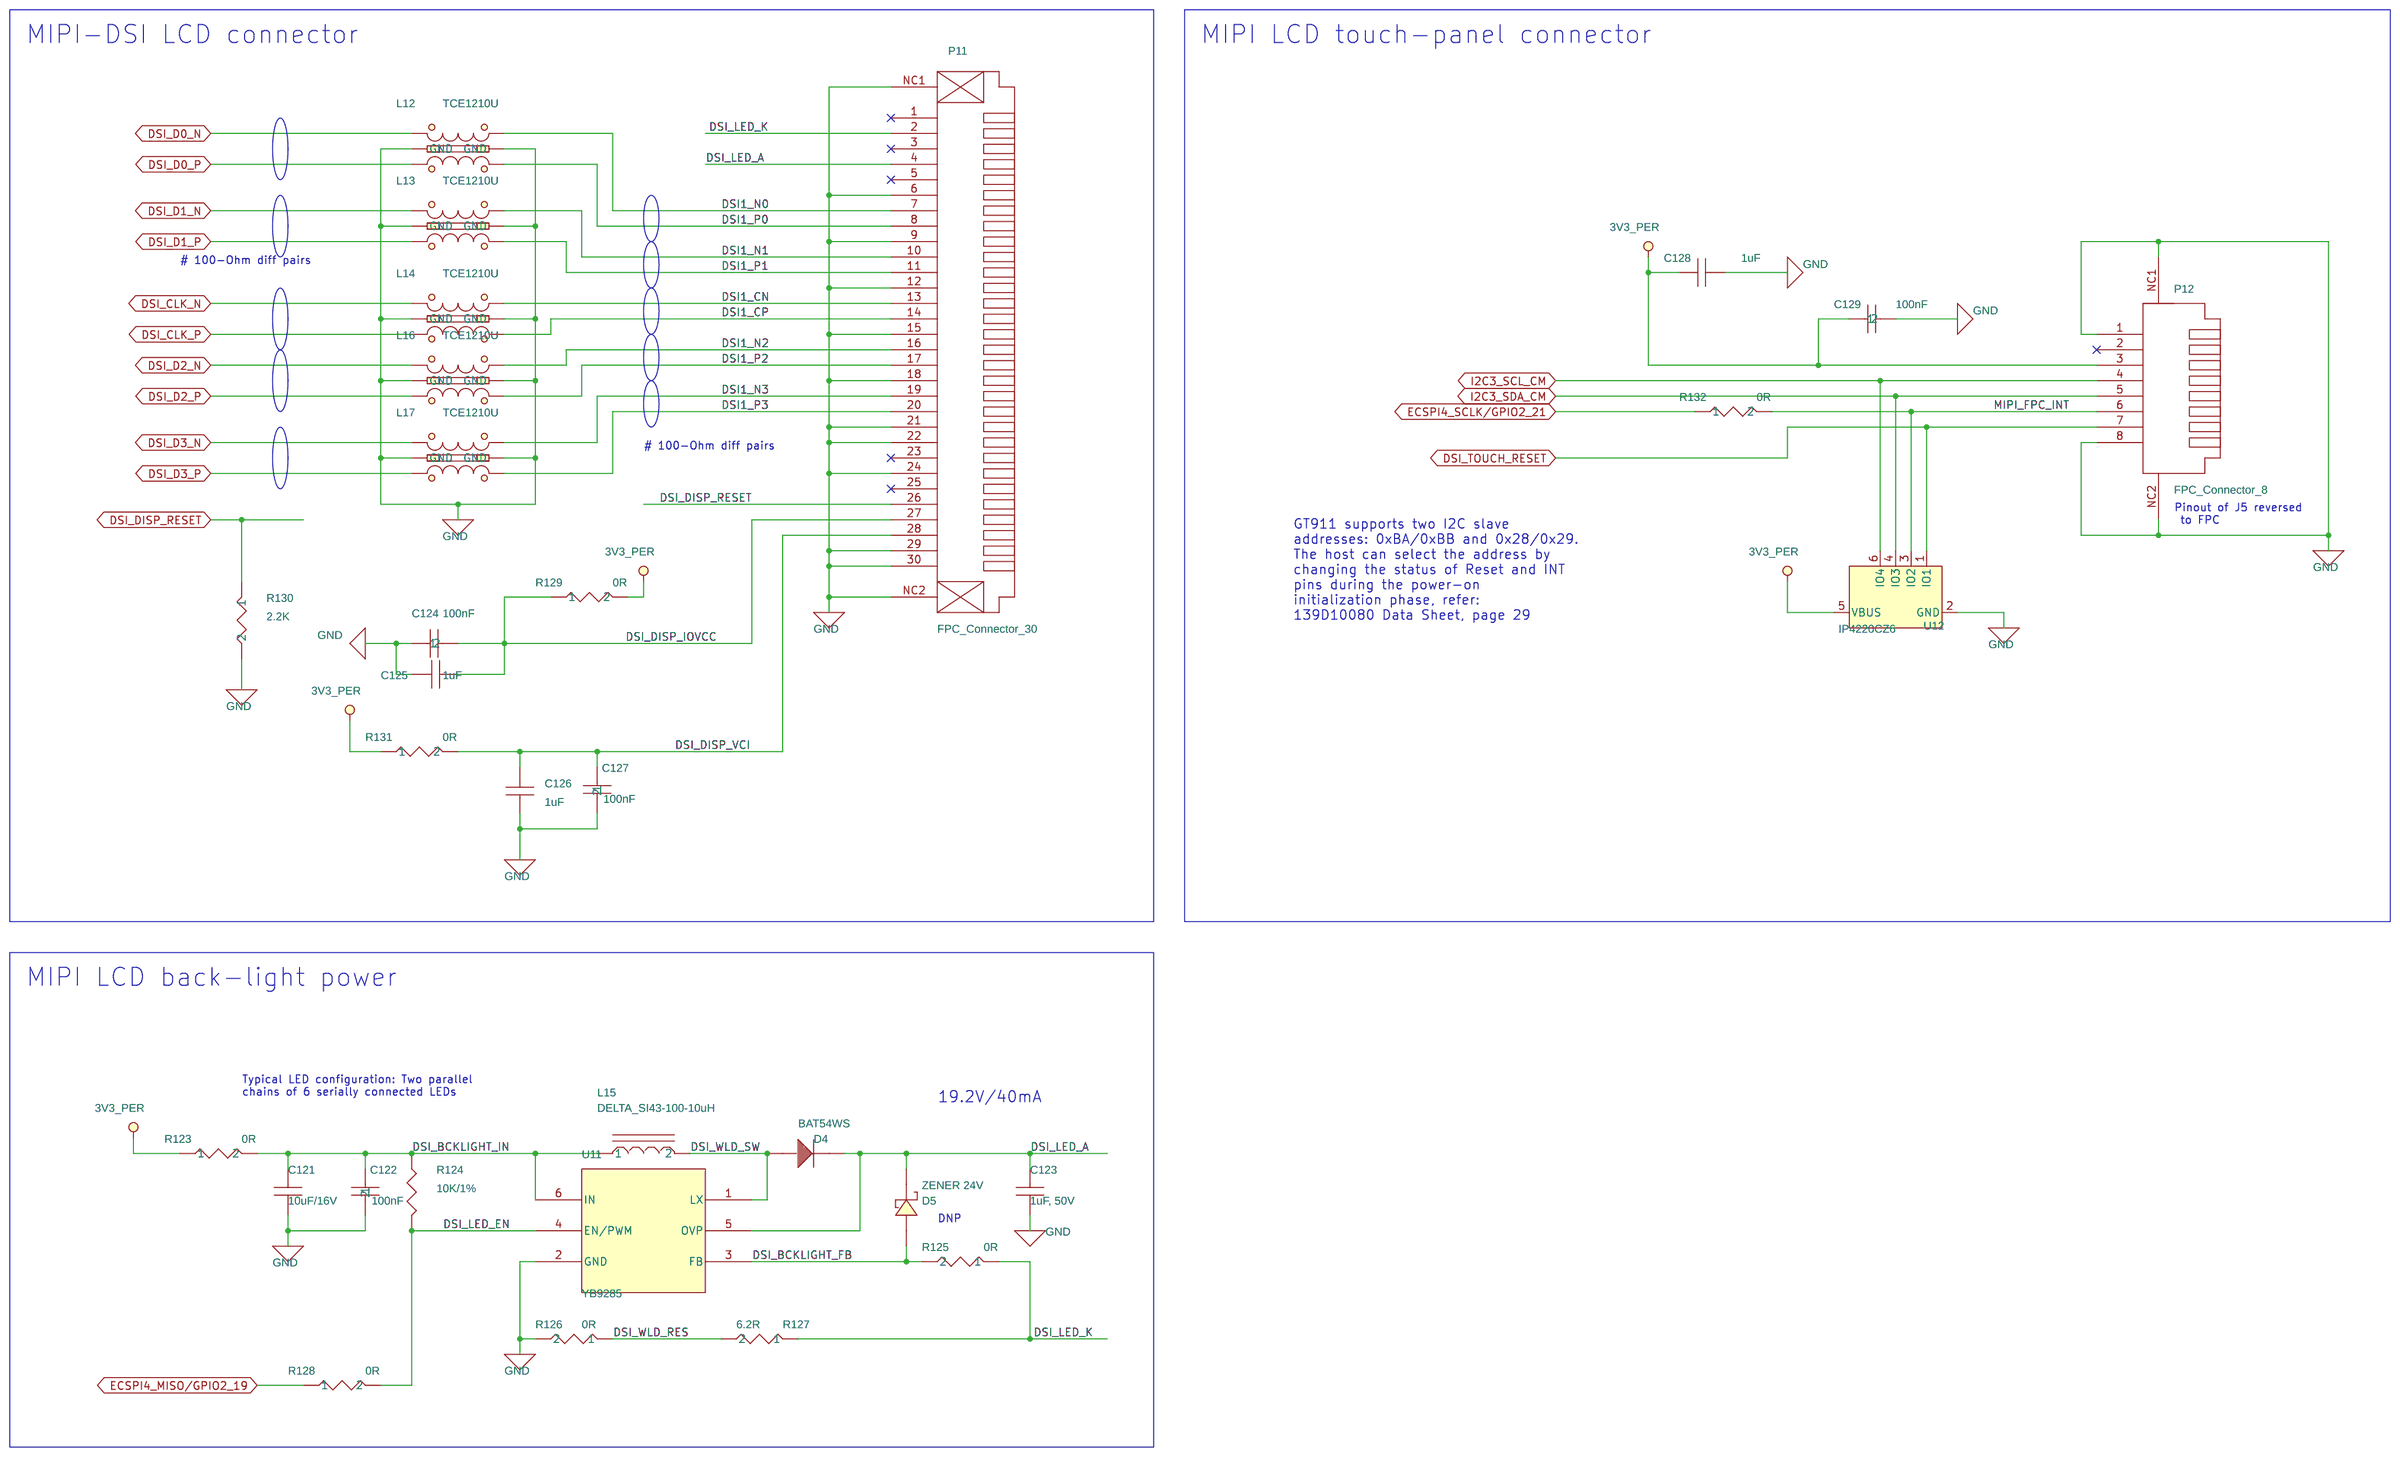
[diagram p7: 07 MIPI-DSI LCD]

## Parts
sheet 01 Index and Block Diagram
PCB1  PCB, SB-UCMIMX93, Rev 1.0
ZZ1  PARSER_VERSION_1.0
sheet 02 SOM Connectors
C37  100nF  [RC0402]
C38  100nF  [RC0402]
C39  100nF  [RC0402]
C40  100nF  [RC0402]
C41  100nF  [RC0402]
C42  100nF  [RC0402]
C43  100nF  [RC0402]
C44  100nF  [RC0402]
C45  10uF/10V  [0402]
C46  10uF/10V  [0402]
C47  10uF/10V  [0402]
C48  10uF/10V  [0402]
C49  100nF  [RC0402]
C50  100nF  [RC0402]
C51  100nF  [RC0402]
C52  100nF  [RC0402]
C53  100nF  [RC0402]
C224  10uF/10V  [0402]
C225  10uF/10V  [0402]
E2  HDR1X2  [1X2THHDR]
E7  HDR1X2  [1X2THHDR]
P1  Hirose DF40C-100DP-0.4V (1.5mm / 3.0mm stacking heights)  [B2B04M2X50P]
P2  Hirose DF40C-100DP-0.4V (1.5mm / 3.0mm stacking heights)  [B2B04M2X50P]
R33  0R  [RC0402]
R35  0R  [RC0402]
R36  0R  [RC0402]
R39  1k, 1%  [RC0402]
R45  1k, 1%  [RC0402]
SW1  PushB  [TACTSW6x6SM]
SW2  PushB  [TACTSW6x6SM]
SW3  PushB  [TACTSW6x6SM]
SW4  PushB  [TACTSW6x6SM]
TP3  TESTPOINT SMT  [TESTPOINT]
TP4  TESTPOINT SMT  [TESTPOINT]
TP5  TESTPOINT SMT  [TESTPOINT]
TP7  TESTPOINT SMT  [TESTPOINT]
TP8  TESTPOINT SMT  [TESTPOINT]
TP9  TESTPOINT SMT  [TESTPOINT]
sheet 05 USB2, JTAG, SPDIF
C34  10nF  [RC0402]
C35  10nF  [RC0402]
C36  100pF  [RC0402]
C54  100nF  [RC0402]
C218  100nF  [RC0402]
C219  1uF,16V  [RC0402]
C220  22uF/25V  [C0805]
C221  100nF  [RC0402]
C232  100nF  [RC0402]
D1  BAT54WS  [SOD-323]
E11  HDR1X2  [1X2THHDR]
J6  USBConn_typeA  [USB-A-SM]
L25  TCE1210U  [EMI1012-ESD]
P4  DR10SM  [2X5SMHDR]
R25  10K  [RC0402]
R26  100R  [RC0402]
R27  100R/1%  [RC0402]
R28  0R  [RC0402]
R29  100R/1%  [RC0402]
R30  220R  [RC0402]
R41  0R  [RC0402]
R42  0R  [RC0402]
R46  10K/1%  [RC0402]
R47  0R  [RC0402]
R48  0R  [RC0402]
R49  0R  [RC0402]
R217  0R  [RC0402]
R220  0R  [RC0402]
R221  10K/1%  [RC0402]
R222  10k  [RC0402]
R224  200K/1%  [RC0402]
U2  74LCX04  [TSSOP-14]  (sections A,B)
U30  USB2.0 mux  [MO-255U1418E]
U31  RT9703,3A Power switch  [SO8-150]
U32  74AUP1G07  [SC70]
sheet 06 CAN, RS485, GPIO, MISC
C55  100nF  [RC0402]
C56  100nF  [RC0402]
C57  10uF/10V  [RC0402]
C58  10uF/10V  [RC0402]
C59  100nF  [RC0402]
C60  4.7uF 10V  [RC0402]
C207  100nF  [RC0402]
C226  100nF  [RC0402]
C233  100nF  [RC0402]
E12  HDR1X2  [1X2THHDR]
J21  Terminal Block Header  [TB2.54mmRA-2x5P]
J22  Terminal Block Header  [TB2.54mmRA-2x5P]
J23  Terminal Block Plug
J24  Terminal Block Plug
P3  DR34SM  [2X17SMHDR]
P5  DR10SM  [2X5SMHDR]
Q3  P-MOS, 1.5A, 8V  [SOT23]
R51  0R  [RC0402]
R52  0R  [RC0402]
R53  0R  [RC0402]
R54  10K/1%  [RC0402]
R55  0R  [RC0402]
R56  0R  [RC0402]
R57  0R  [RC0402]
R58  0R  [RC0402]
R59  1K/1%  [RC0402]
R60  0R  [RC0402]
R61  1K/1%  [RC0402]
R62  0R  [RC0402]
R63  1K/1%  [RC0402]
R64  0R  [RC0402]
R65  0R  [RC0402]
R66  0R  [RC0402]
R67  0R  [RC0402]
R68  0R  [RC0402]
R69  0R  [RC0402]
R70  0R  [RC0402]
R71  0R  [RC0402]
R72  0R  [RC0402]
R73  10K/1%  [RC0402]
R75  0R  [RC0402]
R76  4.75K/1%  [RC0402]
R77  10K/1%  [RC0402]
R78  4.75K/1%  [RC0402]
R79  0R  [RC0402]
R80  0R  [RC0402]
R81  60.4R/1%  [RC0402]
R82  60.4R/1%  [RC0402]
R83  0R  [RC0402]
R84  10K  [RC0402]
R104  0R  [RC0402]
R105  0R  [RC0402]
R195  750R/1%  [RC0402]
R196  4.75K  [RC0402]
R197  750R/1%  [RC0402]
R200  120R/1%  [RC0603]
RN1  10K/8P4R  [RESNET8P0805]
U3  PCA9555  [QFN4x4-24]
U4  ATA6563  [SOI8-150]
U25  MAX13488  [SO8-150]
sheet 07 MIPI-DSI LCD
C121  10uF/16V  [RC0603]
C122  100nF  [RC0402]
C123  1uF, 50V  [RC0603]
C124  100nF  [RC0402]
C125  1uF  [RC0402]
C126  1uF  [RC0402]
C127  100nF  [RC0402]
C128  1uF  [RC0402]
C129  100nF  [RC0402]
D4  BAT54WS  [SOD-323]
D5  ZENER 24V  [SOD-123]
L12  TCE1210U  [EMI1012-ESD]
L13  TCE1210U  [EMI1012-ESD]
L14  TCE1210U  [EMI1012-ESD]
L15  DELTA_SI43-100-10uH  [IND4x4x2_5]
L16  TCE1210U  [EMI1012-ESD]
L17  TCE1210U  [EMI1012-ESD]
P11  FPC_Connector_30  [FPC_30]
P12  FPC_Connector_8  [FPC_8]
R123  0R  [RC0402]
R124  10K/1%  [RC0402]
R125  0R  [RC0402]
R126  0R  [RC0402]
R127  6.2R  [RC0402]
R128  0R  [RC0402]
R129  0R  [RC0402]
R130  2.2K  [RC0402]
R131  0R  [RC0402]
R132  0R  [RC0402]
U11  YB9285  [SOT23-6L]
U12  IP4220CZ6  [SOT23-6L]
sheet 08 LVDS LCD
C61  1uF  [RC0402]
C62  1uF  [RC0402]
C63  100nF  [RC0402]
C64  10uF/16V  [RC0603]
C65  100nF  [RC0402]
C66  1uF, 50V  [RC0603]
C67  220nF  [RC0402]
C68  10uF/16V  [RC0603]
C69  1uF  [RC0402]
C70  100nF  [RC0402]
D3  BAT54WS  [SOD-323]
L6  TCE1210U  [EMI1012-ESD]
L7  TCE1210U  [EMI1012-ESD]
L8  DELTA_SI43-100-10uH  [IND4x4x2_5]
L9  TCE1210U  [EMI1012-ESD]
L10  TCE1210U  [EMI1012-ESD]
L11  TCE1210U  [EMI1012-ESD]
P7  FPC_40_05mm  [FPC05SM40-1]
P8  FPC_Connector_8  [FPC_8]
R85  10K/1%  [RC0402]
R86  0R  [RC1206]
R87  0R  [RC1206]
R88  10K/1%  [RC0402]
R89  0R  [RC1206]
R90  6.2R  [RC0402]
R91  0.75R  [RC0402]
R92  10K/1%  [RC0402]
R93  10K/1%  [RC0402]
R94  10K/1%  [RC0402]
R95  10K/1%  [RC0402]
R96  0R  [RC0402]
R97  10K/1%  [RC0402]
R98  10K/1%  [RC0402]
R99  10K/1%  [RC0402]
R100  10K/1%  [RC0402]
TP6  TESTPOINT  [TESTPOINT]
U5  TPS61165DBVT  [SOT23-6]
U6  IP4220CZ6  [SOT23-6L]
sheet 09 MIPI-CSI Camera Connectors
C102  100nF  [RC0402]
C103  100nF  [RC0402]
C104  100nF  [RC0402]
C105  100nF  [RC0402]
C106  100nF  [RC0402]
C107  10uF  [RC0603]
C108  10uF  [RC0603]
C109  100nF  [RC0402]
C110  100nF  [RC0402]
C111  10uF  [RC0603]
C112  10uF  [RC0603]
C113  100nF  [RC0402]
C114  10uF  [RC0603]
C115  100nF  [RC0402]
C116  100nF  [RC0402]
C117  100nF  [RC0402]
C120  100nF  [RC0402]
E4  HDR1X2  [1X2THHDR]
P9  FPC, 22pin  [FPC05SM22]
P10  Camera_20682-030E-02  [CON30]
R101  10K/1%  [RC0402]
R102  0R  [RC0402]
R103  0R  [RC0402]
R106  10K/1%  [RC0402]
R107  10K/1%  [RC0402]
R108  2.2K  [RC0402]
R109  2.2K  [RC0402]
R110  10K/1%  [RC0402]
R111  10K/1%  [RC0402]
R115  10K/1%  [RC0402]
R116  10K/1%  [RC0402]
R118  0R  [RC0402]
R119  10K/1%  [RC0402]
R120  10K/1%  [RC0402]
R122  0R  [RC0402]
U7  Value  [21-0181B_T423590M-1_MXM]
U8  TXS0102  [MO-187DA-8]
U9  TXS0102  [MO-187DA-8]
sheet 11 Power
Q4  NTZD3154NT  [SOT-563-6]  (sections A,B)
sheet 12 Mechanical
C80  100nF  [RC0402]
C81  100nF  [RC0402]
C82  100nF  [RC0402]
C83  100nF  [RC0402]
C84  100nF  [RC0402]
C85  100nF  [RC0402]
C86  100nF  [RC0402]
C87  100nF  [RC0402]
C88  100nF  [RC0402]
C89  100nF  [RC0402]
C90  100nF  [RC0402]
C91  100nF  [RC0402]
C92  100nF  [RC0402]
C93  100nF  [RC0402]
C94  100nF  [RC0402]
C95  100nF  [RC0402]
C96  100nF  [RC0402]
C97  100nF  [RC0402]
C101  100nF  [RC0402]
H1  HOLE M2  [M2PAD]
H2  HOLE M2  [M2PAD]
H3  HOLE M2  [M2PAD]
H4  HOLE M2  [M2PAD]
H5  HOLE M2  [M2PAD]
JP1  Jumper, black, 100mil
JP2  Jumper, black, 100mil
JP3  Jumper, black, 100mil
JP4  Jumper, black, 100mil
JP5  Jumper, black, 100mil
JP6  Jumper, black, 100mil
JP7  Jumper, black, 100mil
SP1  SMT_SPACER_M2x3  [MINIPCIE-4-Spacer]

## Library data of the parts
PCB1 = PCB,_EM-X270_Rev_1_0.1: CLABCONF0: =SB-UCMIMX93; P/N: 188C04390
ZZ1 = PARSER_VERSION_1_1.0: CLABCONF0: DNP
C37 C116 = 100nF,_10V,_X7R,_10%,_0402_7: CLABCONF0: =SB-UCMIMX93
C38 C113 = 100nF,_10V,_X7R,_10%,_0402_5: CLABCONF0: =SB-UCMIMX93
C39 C70 C103 C124 = 100nF,_10V,_X7R,_10%,_0402_1: CLABCONF0: =SB-UCMIMX93
C40 C55 C63 C115 C127 = 100nF,_10V,_X7R,_10%,_0402: CLABCONF0: =SB-UCMIMX93
C41 C106 = 100nF,_10V,_X7R,_10%,_0402_11: CLABCONF0: =SB-UCMIMX93
C42 C105 = 100nF,_10V,_X7R,_10%,_0402_10: CLABCONF0: =SB-UCMIMX93
C43 C109 = 100nF,_10V,_X7R,_10%,_0402_8: CLABCONF0: =SB-UCMIMX93
C44 C110 = 100nF,_10V,_X7R,_10%,_0402_6: CLABCONF0: =SB-UCMIMX93
C45 C58 = 10uF_10V_20%_0402_1: CLABCONF0: =SB-UCMIMX93
C46 = 10uF,6.3V,0603,20%X5R_2: CLABCONF0: =SB-UCMIMX93; P/N: 151B10600S
C47 = 10uF,6.3V,0603,20%X5R_3: CLABCONF0: =SB-UCMIMX93; P/N: 151B10600S
C48 = 10uF,6.3V,0603,20%X5R_1: CLABCONF0: =SB-UCMIMX93; P/N: 151B10600S
C49 C120 = 100nF,_10V,_X7R,_10%,_0402_9: CLABCONF0: =SB-UCMIMX93
C50 C102 C129 C232 = 100nF,_10V,_X7R,_10%,_0402_2: CLABCONF0: =SB-UCMIMX93
C51 = 100nF,_10V,_X7R,_10%,_0402_12: CLABCONF0: =SB-UCMIMX93
C52 C104 C221 = 100nF,_10V,_X7R,_10%,_0402_4: CLABCONF0: =SB-UCMIMX93
C53 C54 C65 C117 C122 = 100nF,_10V,_X7R,_10%,_0402_3: CLABCONF0: =SB-UCMIMX93
C224 = 10uF,6.3V,0603,20%X5R: CLABCONF0: =SB-UCMIMX93; P/N: 151B10600S
C57 C225 = 10uF_10V_20%_0402: CLABCONF0: =SB-UCMIMX93
E2 = HDR_1x2_100MIL_TH_JUMPER_1: CLABCONF0: =SB-UCMIMX93
E4 E7 E11 E12 = HDR_1x2_100MIL_TH_JUMPER: CLABCONF0: =SB-UCMIMX93
P1 = Hirose_DF40C-100DP-0_0.4V: CLABCONF0: =SB-UCMIMX93; P/N: 182K10004S
P2 = Hirose_DF40C-100DP-0_1.4V: CLABCONF0: =SB-UCMIMX93; P/N: 182K10004S
R33 = 0R,_0402_0_2: CLABCONF0: =SB-UCMIMX93; P/N: 161C00005S
R35 R104 = 0R,_0402_0_1: CLABCONF0: =SB-UCMIMX93; P/N: 161C00005S
R36 = 0R,_0402_0: CLABCONF0: DNP; P/N: 161C00005S
R39 R45 = RESISTOR: CLABCONF0: =SB-UCMIMX93; P/N: 161C10011S
SW1-SW4 = TACT_SW_6x6mm_SMT: CLABCONF0: =SB-UCMIMX93
TP3-TP5 TP7-TP9 = TESTPOINT: CLABCONF0: DNP; P/N: 188Z01370S
C34 = 10nF,_25V,_X7R,_10%,_0402: CLABCONF0: =SB-UCMIMX93
C35 = 10nF,_25V,_X7R,_10%,_0402_1: CLABCONF0: =SB-UCMIMX93
C36 = 100pF,_50V,_NPO,_5%,_0402: CLABCONF0: =SB-UCMIMX93
C218 = 100nF,_10V,_X7R,_10%,_0402: CLABCONF0: =SB-UCMIMX93; Group: LAN2
C219 = 100nF,_10V,_X7R,_10%,_0402_1: CLABCONF0: =SB-UCMIMX93; P/N: 151C10500S
C220 = 22uF,25V,_0805: CLABCONF0: =SB-UCMIMX93
D1 D3 D4 = BAT54WS_0: CLABCONF0: =SB-UCMIMX93
J6 = USB_Conn.,_Fem,_Type_A_,_TH,_RA: CLABCONF0: =SB-UCMIMX93
L6 L7 L9-L14 L16 L17 L25 = ESD_CHOKE_DIFFx2_10: CLABCONF0: =SB-UCMIMX93; P/N: 142D11801S
P4 P5 = HDR_2x5_100MIL_SMT: CLABCONF0: =SB-UCMIMX93
R25 R77 R116 = 10K,1%,0402,1_16W: CLABCONF0: =SB-UCMIMX93
R26 = 100R,1%,0402,1_16W_2: CLABCONF0: =SB-UCMIMX93
R27 = 100R,1%,0402,1_16W_1: CLABCONF0: =SB-UCMIMX93
R28 = 0R,_0402_0: CLABCONF0: =SB-UCMIMX93
R29 = 100R,1%,0402,1_16W: CLABCONF0: =SB-UCMIMX93
R30 = 220R,5%,0402,1_16W: CLABCONF0: =SB-UCMIMX93
R41 R83 = 0R,_0402_1_4: CLABCONF0: DNP
R42 R64 = 0R,_0402_1_2: CLABCONF0: =SB-UCMIMX93
R46 = 10K,1%,0402,1_16W_0: CLABCONF0: DNP
R47 R52 R123 = 0R,_0402_1: CLABCONF0: =SB-UCMIMX93
R48 = 0R,_0402_1_3: CLABCONF0: DNP
R49 = 0R,_0402_1_1: CLABCONF0: DNP
R132 R217 = 0R,_0402: CLABCONF0: =SB-UCMIMX93
R103 R220 = 0R,_0402_1: CLABCONF0: DNP
R84 R221 = 10K,1%,0402,1_16W_0_1: CLABCONF0: =SB-UCMIMX93
R222 = 1M_,5%,_0402: CLABCONF0: =SB-UCMIMX93; P/N: 161C10021S
R224 = 100K,_1%,_0402,_1_16W: CLABCONF0: =SB-UCMIMX93; P/N: 161C20031S
U2 = 74LCX04_sgl_gate_TSSOP-14: CLABCONF0: =SB-UCMIMX93
U30 = USB2_0.0_mux_v2: CLABCONF0: =SB-UCMIMX93; P/N: 116A72220S
U31 = RT9703,3A_Power_switch+FLG: CLABCONF0: =SB-UCMIMX93; P/N: 124S10080S
U32 = 74AUP1G07_,_buffer_,LV: CLABCONF0: =SB-UCMIMX93
C56 C59 C207 C226 C233 = 100nF,_10V,_X7R,_10%,_0402_0: CLABCONF0: =SB-UCMIMX93
C60 = 4.7uF_0402_10V_20%: CLABCONF0: =SB-UCMIMX93
J21 = Terminal_Block_Header_2x5P_2.54_1: CLABCONF0: =SB-UCMIMX93
J22 = Terminal_Block_Header_2x5P_2.54: CLABCONF0: =SB-UCMIMX93
J23 J24 = Terminal_Block_Plug: CLABCONF0: =SB-UCMIMX93; P/N: 178A01000
P3 = HDR_2x17_100MIL_SMT: CLABCONF0: =SB-UCMIMX93
Q3 = P-MOS,_1.5A,_8V: CLABCONF0: =SB-UCMIMX93
R51 = 0R,_0402_1_7: CLABCONF0: =SB-UCMIMX93
R53 = 0R,_0402_1_15: CLABCONF0: =SB-UCMIMX93
R54 = 10K,1%,0402,1_16W_0_2: CLABCONF0: =SB-UCMIMX93
R55 = 0R,_0402_1_16: CLABCONF0: =SB-UCMIMX93
R56 R118 = 0R,_0402_0_2: CLABCONF0: DNP; P/N: 161C00005S
R57 = 0R,_0402_1_18: CLABCONF0: =SB-UCMIMX93
R58 = 0R,_0402_1_14: CLABCONF0: =SB-UCMIMX93
R59 = 1K,1%,0402,1_16W_2: CLABCONF0: DNP; Group: CAN
R60 = 0R,_0402_1_3: CLABCONF0: =SB-UCMIMX93
R61 = 1K,1%,0402,1_16W: CLABCONF0: DNP; Group: CAN
R62 = 0R,_0402_1_1: CLABCONF0: =SB-UCMIMX93
R63 = 1K,1%,0402,1_16W_1: CLABCONF0: DNP; Group: CAN
R65 = 0R,_0402_1_17: CLABCONF0: =SB-UCMIMX93
R66 = 0R,_0402_1_9: CLABCONF0: =SB-UCMIMX93
R67 = 0R,_0402_1_11: CLABCONF0: =SB-UCMIMX93
R68 = 0R,_0402_1_13: CLABCONF0: DNP
R69 = 0R,_0402_1_5: CLABCONF0: =SB-UCMIMX93
R70 = 0R,_0402_1_6: CLABCONF0: =SB-UCMIMX93
R71 = 0R,_0402_1_8: CLABCONF0: =SB-UCMIMX93
R72 = 0R,_0402_1_10: CLABCONF0: =SB-UCMIMX93
R73 R101 = 10K,1%,0402,1_16W_2: CLABCONF0: =SB-UCMIMX93
R75 = 0R,_0402_1_12: CLABCONF0: =SB-UCMIMX93
R76 = 4_0.75K,1%,0402,1_16W: CLABCONF0: =SB-UCMIMX93
R78 = 4_0.75K,1%,0402,1_16W_1: CLABCONF0: =SB-UCMIMX93
R79 R122 = 0R,_0402_0: CLABCONF0: =SB-UCMIMX93; P/N: 161C00005S
R80 = 0R,_0402_0_3: CLABCONF0: =SB-UCMIMX93; P/N: 161C00005S
R81 = 60.4R_1%,_0402_1: CLABCONF0: =SB-UCMIMX93
R82 = 60.4R_1%,_0402: CLABCONF0: =SB-UCMIMX93
R105 = 0R,_0402_0_4: CLABCONF0: =SB-UCMIMX93; P/N: 161C00005S
R195 = 10K,1%,0402,1_16W_1: CLABCONF0: =SB-UCMIMX93; P/N: 161C75001S
R196 = 10K,1%,0402,1_16W_0: CLABCONF0: =SB-UCMIMX93; Group: Always; P/N: 161C47511S
R197 = 10K,1%,0402,1_16W_3: CLABCONF0: =SB-UCMIMX93; P/N: 161C75001S
R200 = 120R_1%,_0603: CLABCONF0: =SB-UCMIMX93
RN1 = RN,10K,8P4R@0805: CLABCONF0: =SB-UCMIMX93
U3 = PCA9555_1: CLABCONF0: =SB-UCMIMX93
U4 = ATA6563: CLABCONF0: =SB-UCMIMX93; P/N: 116A00380S
U25 = SN65HVD72D_0: CLABCONF0: =SB-UCMIMX93; P/N: 116A00430S
C68 C121 = 10uF,6.3V,0603,20%X5R: CLABCONF0: =SB-UCMIMX93
C66 C123 = 1uF,X5R,6.3V,0402: CLABCONF0: =SB-UCMIMX93; P/N: 151D10510S
C61 C69 C125 C126 C128 = 1uF,X5R,6.3V,0402: CLABCONF0: =SB-UCMIMX93
D5 = ZENER_24V_500mW_SOD-123: CLABCONF0: DNP
L8 L15 = INC_DELTA_SI43-100,_10uH: CLABCONF0: =SB-UCMIMX93; CLABCONF1: <null>
P11 = FPC_Connector_0: CLABCONF0: =SB-UCMIMX93; P/N: 182P03002S
P12 = FPC_Connector_4: CLABCONF0: =SB-UCMIMX93; P/N: 182P00802S
R88 R124 = 10K,1%,0402,1_16W_0: CLABCONF0: =SB-UCMIMX93
R125 = 0R,_0402_5: CLABCONF0: =SB-UCMIMX93
R126 = 2.2R,5%,0402,1_16W: CLABCONF0: =SB-UCMIMX93; P/N: 161C00005S
R127 = 2.2R,5%,0402,1_16W_1: CLABCONF0: =SB-UCMIMX93; P/N: 161C06R25S
R128 = 0R,_0402_3: CLABCONF0: DNP
R129 = 0R,_0402_2: CLABCONF0: =SB-UCMIMX93
R108 R130 = 2.2K,5%,0402.1_16W: CLABCONF0: =SB-UCMIMX93
R131 = 0R,_0402_4: CLABCONF0: =SB-UCMIMX93
U11 = AIC1647_0: CLABCONF0: =SB-UCMIMX93; P/N: 123C40000S
U6 U12 = IP4220CZ6_0: CLABCONF0: =SB-UCMIMX93
C62 = 1uF,X5R,6.3V,0402: CLABCONF0: DNP
C64 = 10uF,6.3V,0603,20%X5R_1: CLABCONF0: =SB-UCMIMX93
C67 = 100nF,_10V,_X7R,_10%,_0402_2: CLABCONF0: =SB-UCMIMX93; P/N: 151C22400S
P7 = FPC_40_05mm: CLABCONF0: =SB-UCMIMX93; P/N: 182P04001S
P8 = FPC_Connector_6: CLABCONF0: =SB-UCMIMX93; P/N: 182P00803S
R85 = 10K,1%,0402,1_16W_0_1: CLABCONF0: DNP
R86 = 0R,_1206_2: CLABCONF0: =SB-UCMIMX93
R87 = 0R,_1206: CLABCONF0: =SB-UCMIMX93
R89 = 0R,_1206_1: CLABCONF0: =SB-UCMIMX93
R90 = 2.2R,5%,0402,1_16W: CLABCONF0: DNP; P/N: 161C06R25S
R91 = 2.2R,5%,0402,1_16W_2: CLABCONF0: =SB-UCMIMX93; P/N: 161C0R751S
R92 R110 = 10K,1%,0402,1_16W_6: CLABCONF0: =SB-UCMIMX93
R93 = 10K,1%,0402,1_16W: CLABCONF0: DNP
R94 R120 = 10K,1%,0402,1_16W_3: CLABCONF0: =SB-UCMIMX93
R95 = 10K,1%,0402,1_16W_2: CLABCONF0: DNP
R96 = 2.2R,5%,0402,1_16W_1: CLABCONF0: =SB-UCMIMX93; P/N: 161C00005S
R97 = 10K,1%,0402,1_16W_7: CLABCONF0: DNP
R98 R115 = 10K,1%,0402,1_16W_1: CLABCONF0: =SB-UCMIMX93
R99 = 10K,1%,0402,1_16W_5: CLABCONF0: DNP
R100 R119 = 10K,1%,0402,1_16W_4: CLABCONF0: =SB-UCMIMX93
TP6 = TESTPOINT: CLABCONF0: DNP
U5 = TPS61165DBVT: CLABCONF0: =SB-UCMIMX93; P/N: 123C15100S
C107 C108 C111 C112 C114 = 10uF,6_0.3V,0603,20%X5R: CLABCONF0: =SB-UCMIMX93
P9 = FPC,_0.5mm,_22_cont_0.: CLABCONF0: =SB-UCMIMX93; P/N: 182P02201S
P10 = Camera_20682-030E-02: CLABCONF0: =SB-UCMIMX93; P/N: 182K03002S
R102 = 0R,_0402_0_1: CLABCONF0: DNP; P/N: 161C00005S
R106 = 10K,1%,0402,1_16W_5: CLABCONF0: =SB-UCMIMX93
R107 = 10K,1%,0402,1_16W_7: CLABCONF0: =SB-UCMIMX93
R109 = 2.2K,5%,0402.1_16W_1: CLABCONF0: =SB-UCMIMX93
R111 = 10K,1%,0402,1_16W_8: CLABCONF0: =SB-UCMIMX93
U7 = MAX14998ETOT: CLABCONF0: =SB-UCMIMX93
U8 U9 = TXS0102_0: CLABCONF0: =SB-UCMIMX93; P/N: 116A01020S
Q4 = N-MOSFET_Dual: CLABCONF0: =SB-UCMIMX93; P/N: 131D31540S
C80 = 100nF,_10V,_X7R,_10%,_0402: CLABCONF0: =SB-UCMIMX93; P/N: 151B10400S
C81 = 100nF,_10V,_X7R,_10%,_0402_9: CLABCONF0: =SB-UCMIMX93; P/N: 151B10400S
C82 = 100nF,_10V,_X7R,_10%,_0402_10: CLABCONF0: =SB-UCMIMX93; P/N: 151B10400S
C83 = 100nF,_10V,_X7R,_10%,_0402_18: CLABCONF0: =SB-UCMIMX93; P/N: 151B10400S
C84 = 100nF,_10V,_X7R,_10%,_0402_3: CLABCONF0: =SB-UCMIMX93; P/N: 151B10400S
C85 = 100nF,_10V,_X7R,_10%,_0402_12: CLABCONF0: =SB-UCMIMX93; P/N: 151B10400S
C86 = 100nF,_10V,_X7R,_10%,_0402_13: CLABCONF0: =SB-UCMIMX93; P/N: 151B10400S
C87 = 100nF,_10V,_X7R,_10%,_0402_1: CLABCONF0: =SB-UCMIMX93; P/N: 151B10400S
C88 = 100nF,_10V,_X7R,_10%,_0402_11: CLABCONF0: =SB-UCMIMX93; P/N: 151B10400S
C89 = 100nF,_10V,_X7R,_10%,_0402_16: CLABCONF0: =SB-UCMIMX93; P/N: 151B10400S
C90 = 100nF,_10V,_X7R,_10%,_0402_15: CLABCONF0: =SB-UCMIMX93; P/N: 151B10400S
C91 = 100nF,_10V,_X7R,_10%,_0402_5: CLABCONF0: =SB-UCMIMX93; P/N: 151B10400S
C92 = 100nF,_10V,_X7R,_10%,_0402_14: CLABCONF0: =SB-UCMIMX93; P/N: 151B10400S
C93 = 100nF,_10V,_X7R,_10%,_0402_8: CLABCONF0: =SB-UCMIMX93; P/N: 151B10400S
C94 = 100nF,_10V,_X7R,_10%,_0402_2: CLABCONF0: =SB-UCMIMX93; P/N: 151B10400S
C95 = 100nF,_10V,_X7R,_10%,_0402_17: CLABCONF0: =SB-UCMIMX93; P/N: 151B10400S
C96 = 100nF,_10V,_X7R,_10%,_0402_6: CLABCONF0: =SB-UCMIMX93; P/N: 151B10400S
C97 = 100nF,_10V,_X7R,_10%,_0402_7: CLABCONF0: =SB-UCMIMX93; P/N: 151B10400S
C101 = 100nF,_10V,_X7R,_10%,_0402_4: CLABCONF0: =SB-UCMIMX93; P/N: 151B10400S
H1-H5 = Hole,_Plated,_M2,_5mm._ext.: CLABCONF0: DNP
JP1-JP7 = Jumper,_black,_100mil: CLABCONF0: =SB-UCMIMX93
SP1 = SMT_SPACER_M2x3_1: CLABCONF0: =SB-UCMIMX93

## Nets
1V8_PER: C114.1 C115.1 P10.3(VCC_1P8) R42.1 R122.1 ; also on sheet 9 10
3V3_EXP: C55.1 Q3.3(D) R68.1 U3.21(VDD)
3V3_PER: C58.1 C59.1 C61.1 C63.1 C69.1 C70.1 C80.1 C81.1 C82.1 C83.1 C84.1 C85.1 C86.1 C87.1 C88.1 C89.1 C90.1 C102.2 C103.2 C104.2 C105.2 C106.1 C107.1 C108.1 C109.1 C111.1 C112.1 C113.1 C116.1 C128.1 C129.1 C218.2 C226.2 C232.1 E2.2 E4.1 E7.2 P3.2 P7.38 P7.39 P8.3 P9.22 P10.1(VCC1_3P3) P10.2(VCC2_3P3) P12.3 Q3.2(S) R41.2 R54.1 R59.1 R61.1 R63.1 R68.2 R73.2 R76.1 R78.1 R85.2 R92.1 R93.1 R94.1 R95.1 R118.1 R123.1 R129.2 R131.1 R222.2 SW3.1 SW3.3 SW4.1 SW4.3 U2.14(VCC) U4.5(VIO) U6.5(VBUS) U7.1(VDD) U7.6(VDD_1) U7.13(VDD_2) U7.26(VDD_3) U8.7(VCCB) U9.7(VCCB) U12.5(VBUS) U30.9(VCC) ; also on sheet 9 10 11 12
5V0_PER: C56.2 C57.1 C207.2 C219.2 C233.1 P5.10 R86.1 R195.2 R196.2 U4.3(VCC) U25.8(VCC) U31.6(Vin) U31.7(Vin) ; also on sheet 9 10 12
GND: C36.2 C37.2 C38.2 C39.2 C40.2 C41.2 C42.2 C43.2 C44.2 C45.1 C46.1 C47.1 C48.1 C49.2 C50.2 C51.2 C52.2 C53.2 C54.1 C55.2 C56.1 C57.2 C58.2 C59.2 C60.2 C61.2 C62.1 C63.2 C64.2 C65.2 C66.2 C67.2 C69.2 C70.2 C80.2 C81.2 C82.2 C83.2 C84.2 C85.2 C86.2 C87.2 C88.2 C89.2 C90.2 C91.2 C92.2 C93.2 C94.2 C95.2 C96.2 C97.2 C101.2 C102.1 C103.1 C104.1 C105.1 C106.2 C107.2 C108.2 C109.2 C110.2 C111.2 C112.2 C113.2 C114.2 C115.2 C116.2 C117.2 C120.2 C121.2 C122.2 C123.2 C124.1 C125.2 C126.1 C127.2 C128.2 C129.2 C207.1 C218.1 C219.1 C220.2 C221.2 C224.1 C225.1 C226.1 C232.2 C233.2 E11.2 H1.1 H2.1 H3.1 H4.1 H5.1 J6.4(GND) J6.5(SHELL_1) J6.6(SHELL_2) J21.2(2A) J21.CHASSIS J22.2(2A) J22.CHASSIS L6.5(GND) L6.6(GND) L7.5(GND) L7.6(GND) L9.5(GND) L9.6(GND) L10.5(GND) L10.6(GND) L11.5(GND) L11.6(GND) L12.5(GND) L12.6(GND) L13.5(GND) L13.6(GND) L14.5(GND) L14.6(GND) L16.5(GND) L16.6(GND) L17.5(GND) L17.6(GND) L25.5(GND) L25.6(GND) P1.4 P1.10 P1.20 P1.40 P1.54 P1.64 P1.78 P1.88 P2.10 P2.16 P2.22 P2.28 P2.34 P2.40 P2.46 P2.54 P2.72 P2.82 P3.33 P4.4 P4.6 P5.9 P7.11 P7.16 P7.19 P7.22 P7.25 P7.28 P7.31 P7.34 P8.1 P8.8 P8.9 P8.10 P9.1 P9.4 P9.7 P9.10 P9.13 P9.16 P9.19 P9.NC1 P9.NC2 P10.4(GND1) P10.5(GND2) P10.9(GND3) P10.14(GND4) P10.17(GND5) P10.18(GND6) P10.22(GND7) P10.26(GND8) P10.SH1 P10.SH2 P10.SH3 P10.SH4 P10.SH5 P10.SH6 P10.SH7 P10.SH8 P10.SH9 P10.SH10 P10.SH11 P10.SH12 P10.SH13 P10.SH14 P10.SH15 P10.SH16 P10.SH17 P10.SH18 P10.SH19 P11.6 P11.9 P11.12 P11.15 P11.18 P11.21 P11.22 P11.24 P11.29 P11.30 P11.NC1 P11.NC2 P12.1 P12.8 P12.NC1 P12.NC2 Q4.1(S) R29.1 R30.2 R47.1 R77.2 R84.1 R96.2 R97.2 R98.2 R99.2 R100.2 R101.1 R107.1 R111.1 R119.1 R120.1 R126.2 R130.2 R197.1 R217.2 R221.1 R224.2 RN1.2(RB1) RN1.3(RC1) RN1.4(RD1) SP1.NC(1) SW1.1 SW1.3 SW2.1 SW2.3 U2.7(GND) U3.9(VSS) U3.25(CPAD) U4.2(GND) U5.4(GND) U6.2(GND) U7.Tpad U8.2(GND) U9.2(GND) U11.2(GND) U12.2(GND) U25.5(GND) U30.4(GND) U31.4(GND) U32.3(GND) ; also on sheet 9 10 11 12
VBUS_USB_B: C220.1 J6.1(VBUS) R220.1 U31.2(Vout) U31.3(Vout)
VCC_RTC: P1.93 ; also on sheet 9
A_IN: C34.2 R26.2
ADC_IN0: P2.89 P3.9
ADC_IN1: P2.91 P3.11
ADC_IN2: P2.93 P3.13
ADC_IN3: P2.95 P3.15
ALT_BOOT: P1.90 R39.1
AMP_IN: R25.2 R26.1 U2.1(I)
AMP_OUT: R25.1 U2.2(12) U2.3(I)
AMP_SPDIF_RX: R28.1 U2.4(12)
AUD_nINT: R51.1 ; also on sheet 10
BOOT_MODE0: P1.75 P5.1
BOOT_MODE1: P1.80 P5.3
BOOT_MODE2: P1.82 P5.5
BOOT_MODE3: P1.58 P5.7
CAN1_CAP: C60.1 R81.1 R82.2
CAN1_H: J21.1(1A) R81.2 U4.7(CANH)
CAN1_L: J21.3(3A) R82.1 U4.6(CANL)
CAN1_STBY: R83.2 R84.2 U4.8(STBY)
CAN1_STBY_ENL: R69.1 R83.1
CAN2_RX: R105.1 U4.4(RXD)
CAN2_TX: R104.1 U4.1(TXD)
CARRIER_3V3_GPIO0_0: R51.2 U3.1(I/O0.0)
CARRIER_3V3_GPIO0_1: R52.2 U3.2(I/O0.1)
CARRIER_3V3_GPIO0_2: R53.2 U3.3(I/O0.2)
CARRIER_3V3_GPIO0_3: R55.2 U3.4(I/O0.3)
CARRIER_3V3_GPIO0_4: R57.2 U3.5(I/O0.4)
CARRIER_3V3_GPIO0_5: R58.2 U3.6(I/O0.5)
CARRIER_3V3_GPIO0_6: R60.2 U3.7(I/O0.6)
CARRIER_3V3_GPIO0_7: R62.2 U3.8(I/O0.7)
CARRIER_3V3_GPIO1_0: R64.2 U3.10(I/O1.0)
CARRIER_3V3_GPIO1_1: R65.2 U3.11(I/O1.1)
CARRIER_3V3_GPIO1_2: R66.2 U3.12(I/O1.2)
CARRIER_3V3_GPIO1_3: R67.2 U3.13(I/O1.3)
CARRIER_3V3_GPIO1_4: R69.2 U3.14(I/O1.4)
CARRIER_3V3_GPIO1_5: R70.2 U3.15(I/O1.5)
CARRIER_3V3_GPIO1_6: R71.2 U3.16(I/O1.6)
CARRIER_3V3_GPIO1_7: R72.2 U3.17(I/O1.7)
CSI1_B_FLASH_OUT: R66.1 U8.1(B2)
CSI1_B_FLASH_OUT_1V8: P10.29(FLASH) U8.4(A2)
CSI1_B_RST: R65.1 R116.2
CSI1_B_RST_1V8: P10.21(RESET) R116.1 R120.2
CSI1_B_TRG: R67.1 R102.1 U8.8(B1)
CSI1_B_TRG_1V8: P10.12(TRIGGER) U8.5(A1)
CSI1_GPIO_1V8_ENABLE: R106.1 R107.2 U8.6(OE)
CSI1_I2C_1V8_ENABLE: R110.1 R111.2 U9.6(OE)
CSI1_PWR_DWN_B: R64.1 R115.2
CSI1_PWR_DWN_B_1V8: P10.6(PWDN) R115.1 R119.2
CSI1_SELECTOR: E4.2 R101.2 R106.2 R110.2 U7.16(SEL1) U7.17(SEL2)
CSI_CLK_N: P2.30 U7.5(COM1-)
CSI_CLK_P: P2.32 U7.4(COM1+)
CSI_D0_N: P2.31 U7.8(COM2-)
CSI_D0_P: P2.33 U7.7(COM2+)
CSI_D1_N: P2.35 U7.10(COM3-)
CSI_D1_P: P2.37 U7.9(COM3+)
CSI_P22_CKN: P9.8 U7.39(NC1-)
CSI_P22_CKP: P9.9 U7.40(NC1+)
CSI_P22_DN0: P9.2 U7.37(NC2-)
CSI_P22_DN1: P9.5 U7.35(NC3-)
CSI_P22_DP0: P9.3 U7.38(NC2+)
CSI_P22_DP1: P9.6 U7.36(NC3+)
CSI_P30_CKN: P10.24(MIPI_CLK_N) U7.31(NO1-)
CSI_P30_CKP: P10.25(MIPI_CLK_P) U7.32(NO1+)
CSI_P30_DN0: P10.19(MIPI_D0_N) U7.29(NO2-)
CSI_P30_DN1: P10.15(MIPI_D1_N) U7.27(NO3-)
CSI_P30_DP0: P10.20(MIPI_D0_P) U7.30(NO2+)
CSI_P30_DP1: P10.16(MIPI_D1_P) U7.28(NO3+)
DSI1_CN: L14.2 P11.13
DSI1_CP: L14.1 P11.14
DSI1_N0: L12.2 P11.7
DSI1_N1: L13.2 P11.10
DSI1_N2: L16.2 P11.16
DSI1_N3: L17.2 P11.19
DSI1_P0: L12.1 P11.8
DSI1_P1: L13.1 P11.11
DSI1_P2: L16.1 P11.17
DSI1_P3: L17.1 P11.20
DSI_BCKLIGHT_FB: D5.2(ANODE) R125.2 U11.3(FB)
DSI_BCKLIGHT_IN: C121.1 C122.1 L15.1 R123.2 R124.1 U11.6(IN)
DSI_CLK_N: L14.3 P2.21
DSI_CLK_P: L14.4 P2.23
DSI_D0_N: L12.3 P2.1
DSI_D0_P: L12.4 P2.3
DSI_D1_N: L13.3 P2.15
DSI_D1_P: L13.4 P2.17
DSI_D2_N: L16.3 P2.5
DSI_D2_P: L16.4 P2.7
DSI_D3_N: L17.3 P2.11
DSI_D3_P: L17.4 P2.13
DSI_DISP_IOVCC: C124.2 C125.1 P11.27 R129.1
DSI_DISP_RESET: P11.26 R57.1 R130.1
DSI_DISP_VCI: C126.2 C127.1 P11.28 R131.2
DSI_LED_A: C123.1 D4.CATHODE D5.1(CATHODE) P11.4 U11.5(OVP)
DSI_LED_EN: R124.2 R128.2 U11.4(EN/PWM)
DSI_LED_K: P11.2 R125.1 R127.1
DSI_TOUCH_RESET: P12.7 R58.1 U12.1(IO1)
DSI_WLD_RES: R126.1 R127.2
DSI_WLD_SW: D4.ANODE L15.2 U11.1(LX)
ECSPI3_MISO/UART7_RX: P1.41 U25.1(RO)
ECSPI3_MOSI: P1.35 P3.14
ECSPI3_SCLK: P1.37 P3.16
ECSPI3_SS0/UART7_TX: P1.39 U25.4(DI)
ECSPI4_MISO/GPIO2_19: P1.59 R128.1
ECSPI4_MOSI/GPIO2_20: P1.61 P8.6 U6.4(IO3)
ECSPI4_SCLK/GPIO2_21: P1.63 R132.1
ECSPI4_SS0: P1.89 P3.17
ENET1_MDC_CM: P2.60 TP7.1
ENET1_MDIO_CM: P2.62 TP8.1
ENET1_TD2_CM: P2.77 TP9.1
ENET2_MDC: P2.68 ; also on sheet 10
ENET2_MDIO: P2.70 ; also on sheet 10
ENET2_RD0: P2.41 ; also on sheet 10
ENET2_RD1: P2.43 ; also on sheet 10
ENET2_RD2: P2.45 ; also on sheet 10
ENET2_RD3: P2.47 ; also on sheet 10
ENET2_RX_CTL: P2.53 ; also on sheet 10
ENET2_RXC: P2.55 ; also on sheet 10
ENET2_TD0: P2.59 ; also on sheet 10
ENET2_TD1: P2.61 ; also on sheet 10
ENET2_TD2: P2.65 ; also on sheet 10
ENET2_TD3: P2.63 ; also on sheet 10
ENET2_TX_CTL: P2.67 ; also on sheet 10
ENET2_TXC: P2.69 ; also on sheet 10
ETH1_LED_ACT/PHY1ADDRESS2: P2.83 ; also on sheet 10
ETH1_LINK-LED_10_100: P2.86 ; also on sheet 10
ETH1_LINK-LED_1000/INTSELECT: P2.75 ; also on sheet 10
ETH1_MDI0N: P2.73 ; also on sheet 10
ETH1_MDI0P: P2.74 ; also on sheet 10
ETH1_MDI1N: P2.80 ; also on sheet 10
ETH1_MDI1P: P2.78 ; also on sheet 10
ETH1_MDI2N: P2.81 ; also on sheet 10
ETH1_MDI2P: P2.79 ; also on sheet 10
ETH1_MDI3N: P2.85 ; also on sheet 10
ETH1_MDI3P: P2.84 ; also on sheet 10
EXP_nPWREN: Q4.2(G) R75.2 R77.1
EXP_nPWREN_G: Q3.1(G) Q4.6(D) R73.1
EXPANDER_A0: R59.2 RN1.5(RD2) U3.18(A0)
EXPANDER_A1: R61.2 RN1.6(RC2) U3.23(A1)
EXPANDER_A2: R63.2 RN1.7(RB2) U3.24(A2)
EXTEN_GPIO_1: R52.1 ; also on sheet 10
EXTEN_GPIO_2: R53.1 ; also on sheet 10
FPC22_17: P9.17 R102.2
FPC22_18: P9.18 R103.1
GPIO_IO00: P1.28 P3.3
GPIO_IO01: P1.26 P3.1
GPIO_IO02: P1.30 P3.5
GPIO_IO03: P1.32 P3.7
GPIO_IO04: P2.58 P3.20
GPIO_IO05: P2.56 P3.18
GPIO_IO07: P1.98 P3.6
GPIO_IO13: P1.100 R88.2 U5.2(CTRL)
GPIO_IO14: P2.76 P5.4
GPIO_IO15: P1.60 P5.2
GPIO_IO16: P1.96 P3.4
GPIO_IO17: P1.95 P3.19
GPIO_IO22/SPDIF_RX: P1.79 R28.2
GPIO_IO23/SPDIF_TX: C35.2 P1.81
GPIO_IO25/CAN2_TX: P1.33 R104.2
GPIO_IO27/CAN2_RX: P1.49 R105.2
HASW_EN: E11.1 R222.1 U30.10(SEL) U31.5(EN)
HASW_IP2: R224.1 U31.8(IP)
HOSTB_USB_DN: J6.2(D-) L25.4
HOSTB_USB_DP: J6.3(D+) L25.3
HUB_OE: R221.2 U30.8(\\~{O}E)
I2C3_SCK: P1.94 P3.32 R79.2
I2C3_SCL_1V8: P10.7(I2C_SCL) R109.1 U9.4(A2)
I2C3_SCL_CM: P8.4 P9.20 P12.4 R76.2 R79.1 U3.19(SCL) U6.1(IO1) U9.1(B2) U12.6(IO4) ; also on sheet 10 11
I2C3_SDA: P1.91 P3.34 R80.2
I2C3_SDA_1V8: P10.8(I2C_SDA) R108.1 U9.5(A1)
I2C3_SDA_CM: P8.5 P9.21 P12.5 R78.2 R80.1 U3.20(SDA) U6.3(IO2) U9.8(B1) U12.4(IO3) ; also on sheet 10 11
INT_EXP: R54.2 R56.1 U3.22(\\~{IN}T)
JTAG_HDR_10: P4.10 R47.2
JTAG_POWER: C54.2 C221.1 D1.ANODE P4.2 R41.1 R42.2 U32.5(VCC)
JTAG_RST: P4.9 R46.2 U32.2(IN)
JTAG_RST_PU: D1.CATHODE R46.1
JTAG_TCK: P1.73 P4.3
JTAG_TDI: P1.71 P4.7
JTAG_TDO: P1.67 P4.5
JTAG_TMS: P1.65 P4.1
JTAGRST_OD: R48.1 R49.1 U32.4(OUT)
LVDS_CLK_N: L11.3 P2.14
LVDS_CLK_P: L11.4 P2.12
LVDS_CLKN: L11.2 P7.24
LVDS_CLKP: L11.1 P7.23
LVDS_COMP: C67.1 U5.5(COMP)
LVDS_DIMO: P7.14 TP6.1
LVDS_DISP_RESET: C62.2 P7.36 R60.1 R85.1
LVDS_L_R: P7.8 R92.2 R97.1
LVDS_LED_N: R89.2 R90.1 R91.1 U5.6(FB)
LVDS_LED_NEG: C68.1 P7.9 P7.10 R89.1
LVDS_LED_P: C66.1 D3.CATHODE R87.2
LVDS_LED_POS: C68.2 P7.1 P7.2 R87.1
LVDS_N0: L7.1 P7.33
LVDS_N1: L6.1 P7.30
LVDS_N2: L9.1 P7.27
LVDS_N3: L10.1 P7.21
LVDS_P0: L7.2 P7.32
LVDS_P1: L6.2 P7.29
LVDS_P2: L9.2 P7.26
LVDS_P3: L10.2 P7.20
LVDS_RESET: R90.2 R91.2 R96.1
LVDS_SELB: P7.13 R95.2 R100.1
LVDS_STBYB: P7.35 R94.2 R99.1
LVDS_SW_PWR_IN: C64.1 C65.1 L8.1 R86.2 R88.1 U5.1(IN)
LVDS_TOUCH_RESET: P8.7 R62.1 U6.6(IO4)
LVDS_TX0_N: L7.4 P2.26
LVDS_TX0_P: L7.3 P2.24
LVDS_TX1_N: L6.4 P2.20
LVDS_TX1_P: L6.3 P2.18
LVDS_TX2_N: L9.4 P2.8
LVDS_TX2_P: L9.3 P2.6
LVDS_TX3_N: L10.4 P2.4
LVDS_TX3_P: L10.3 P2.2
LVDS_U_D: P7.7 R93.2 R98.1
LVDS_WLD_SW: D3.ANODE L8.2 U5.3(SW)
MIPI_FPC_INT: P12.6 R132.2 U12.3(IO2)
MODEM_RST: R70.1 ; also on sheet 11
mux_PCIe_USB_DN: U30.7(HSD1-) ; also on sheet 11
mux_PCIe_USB_DP: U30.1(HSD1+) ; also on sheet 11
MUX_USB2_DN: L25.1 U30.6(HSD2-)
MUX_USB2_DP: L25.2 U30.2(HSD2+)
PB_ALT_BOOT: E2.1 R39.2 SW3.2 SW3.4
PB_RESET: R35.2 R36.2 SW2.2 SW2.4
PB_SDWN_ENH: E7.1 R45.2 SW4.2 SW4.4
PDM_CLK/GPIO1_8: P1.21 P3.8 R75.1
PDM_DATA0: P1.23 P3.10 R56.2
PDM_DATA1: P1.25 P3.12
PMIC_ON_REQ: P1.68 ; also on sheet 9
PMIC_STBY_REQ: P1.66 ; also on sheet 9
POR_B_3P3: P2.66 R36.1 R49.2
PWRBTN: P2.64 R33.1
RS485_: E12.2 R200.2
RS485_NEG: E12.1 J22.3(3A) R197.2 U25.7(B)
RS485_POS: J22.1(1A) R195.1 R200.1 U25.6(A)
SAI1_RXD0: P1.45 ; also on sheet 10
SAI1_TXC/CAN1_RX: P1.51 ; also on sheet 10
SD2_CLK: P2.96 ; also on sheet 11
SD2_CMD: P2.100 ; also on sheet 11
SD2_DATA0: P2.97 ; also on sheet 11
SD2_DATA1: P2.99 ; also on sheet 11
SD2_DATA2: P2.94 ; also on sheet 11
SD2_DATA3: P2.98 ; also on sheet 11
SD2_nCD: P2.92 ; also on sheet 11
SD2_nRST: P2.51 P3.30
SD3_CLK: P2.36 P3.21
SD3_CMD: P2.38 P3.23
SD3_DATA0: P2.42 P3.25
SD3_DATA1: P2.44 P3.27
SD3_DATA2: P2.48 P3.22
SD3_DATA3: P2.50 P3.24
SDWN_ENH: P2.88 R45.1
SPDIF_AUDIO_IN: C34.1 P3.29 R29.2
SPDIF_AUDIO_OUT: C36.1 P3.31 R27.2 R30.1
SPDIF_OUT1C: C35.1 R27.1
SW_SAI1_TXD0/CAN1_TX: P1.53 ; also on sheet 10
SW_SAI1_TXFS: P1.87 ; also on sheet 10
SW_UART1_TXD: P1.74 ; also on sheet 11
SW_UART2_TXD: P1.72 ; also on sheet 11
SWPWRBTN: R33.2 SW1.2 SW1.4
SYS_RST_PMIC: P1.2 R35.1 R48.2
TAMPER0: P2.25 P3.26
TAMPER1: P2.27 P3.28
TESTPOINT3: P1.84 TP3.1
TESTPOINT4: P1.92 TP4.1
TESTPOINT5: P2.90 TP5.1
U25_RE: R196.1 U25.2(RE) U25.3(\\~{SHD}N)
UART1_RXD: P1.76 ; also on sheet 11
UART2_RXD: P1.19 ; also on sheet 11
USB1_DN: P1.14 ; also on sheet 12
USB1_DP: P1.12 ; also on sheet 12
USB1_ID: P1.22 ; also on sheet 12
USB1_VBUS_3V3: P1.24 ; also on sheet 12
USB2_DN: P1.5 U30.5(D-)
USB2_DP: P1.3 U30.3(D+)
USB2_ID: P1.7 R217.1
USB2_VBUS_3V3: P1.1 R220.2
V_SOM: C37.1 C38.1 C39.1 C40.1 C41.1 C42.1 C43.1 C44.1 C45.2 C46.2 C47.2 C48.2 C49.1 C50.1 C51.1 C52.1 C53.1 C91.1 C92.1 C93.1 C94.1 C95.1 C96.1 C97.1 C101.1 C224.2 C225.2 P1.11 P1.27 P1.43 P1.57 P1.69 P1.83 P2.9 P2.19 P2.29 P2.39 P2.57 P2.71 P2.87 ; also on sheet 9
VIO_CAMERA_CSI1: C110.1 C117.1 C120.1 R108.2 R109.2 R118.2 R122.2 U8.3(VCCA) U9.3(VCCA)
VSD_3V3: P1.17 ; also on sheet 11

Not connected (* = marked no-connect by the designer): J21 4(4A)* 5(5A)* 6(6B)* 7(7B)* 8(8B)* 9(9B)* 10(10B)*; J22 4(4A)* 5(5A)* 6(6B)* 7(7B)* 8(8B)* 9(9B)* 10(10B)*; P1 6* 8* 9* 13* 15* 16* 18* 29* 31* 34* 36* 38* 42* 44* 46* 47* 48* 50* 52* 55* 56* 62* 70* 77* 85* 86* 97* 99*; P2 49* 52*; P4 8*; P5 6* 8*; P7 3* 4* 5* 6* 12* 15* 17* 18* 37* 40*; P8 2*; P9 11 12 14 15; P10 10(MIPI_D2_N)* 11(MIPI_D2_P)* 13(RSVD1)* 23(RSVD2)* 27(MIPI_D3_N)* 28(MIPI_D3_P)* 30(RSVD3)*; P11 1* 3* 5* 23* 25*; P12 2*; R55 1*; R71 1*; R72 1*; R103 2*; RN1 1(RA1)* 8(RA2)*; U7 2(COM0+)* 3(COM0-)* 11(COM4+)* 12(COM4-)* 14(COM5+)* 15(COM5-)* 18(NO5-)* 19(NO5+)* 20(NO4-)* 21(NO4+)* 22(NC5-)* 23(NC5+)* 24(NC4-)* 25(NC4+)* 33(NO0-)* 34(NO0+)* 41(NC0-)* 42(NC0+)*; U31 1(FLG)*

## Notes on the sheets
sheet 1
- SB-UCMIMX93
- BOARD REVISION: 1.0
- Page
- Description
- 01
- Index and Block Diagram
- 02
- SOM Connectors
- 03
- Ethernet and Expansion conn.
- 04
- USB1
- 05
- USB2, JTAG, SPDIF
- 06
- CAN, RS485, GPIO, MISC
- 07
- MIPI-DSI LCD
- 08
- LVDS LCD
- 09
- MIPI-CSI Camera Connectors
- 10
- Console, RS232, SD, miniPCIe
- 11
- Power
- 12
- Mechanical
sheet 2
- USB2
- Host with mux for miniPCIe socket P18
- NOTE: USB1 multiplexing is controlled by jumper E11
- # 90-Ohm diff pairs
- 1.05A LIMIT
- E11 operation
  Open:       for USB conn. J6
  Close:      for miniPCIe socket P18
- SPDIF
- JTAG
- NXP refdes layout
- DNP
- TMS
- VCC
- TCK
- GND
- TDI
- TDO
- GND
- SILKSCREEN:
  JTAG
- DNP
- DNP
sheet 3
- SOM connectors
- Power button
- UART5_RXD_BT
- UART5_CTS_BT
- UART5_TXD_BT
- UART5_RTS_BT
- DNP
- RESET
- SD boot
- A53 core console
- RESERVED#1
- RESERVED#2
- SDP (USB) boot
- RESERVED#3
sheet 4
- CAN bus
- Miscellaneous header
- UART5_RXD_BT
- w/o WB
  on UCM
- UART5_CTS_BT
- UART5_TXD_BT
- UART5_RTS_BT
- w/o WB
  on UCM
- DNP
- To GPIO Expander
- RS485
- Boot mode header
- #BOOT_MODE0
- #BOOT_MODE1
- #BOOT_MODE2
- #BOOT_MODE3
- UART7_RX
- UART7_TX
- Carrier board I2C
- GPIO expander
- GPIO expander reset
- DNP
- DNP
- ALT 5: gpio1.IO[9]
- DNP
- DNP
- ALT 5: gpio1.IO[8]
- DNP
- I2C Address:
  0x20
sheet 5
- LVDS LCD connector
- LVDS touch panel connector
- DNP
- DNP
- INT
- # 100-Ohm diff pairs
- # 100-Ohm diff pairs
- GT911 supports two I2C slave
  addresses: 0xBA/0xBB and 0x28/0x29.
  The host can select the address by
  changing the status of Reset and INT
  pins during the power-on
  initialization phase, refer:
  139D10090 Data Sheet, page 16
- Pinout of J5 reversed
   to FPC
- DNP
- DNP
- DNP
- DNP
- LVDS LCD back-light power
- 9.6V/270mA
- SPDIF_RX = PWM2_OUT
- DNP
sheet 6
- For PCIe module
- Stitching capacitors
- For Extension Board
- 12  Jumper Plugs
sheet 7
- MIPI-CSI multiplexor
- RPI camera 22-pin connector
- # 100-Ohm diff pairs
- Enable 30-pin,
  1.8V connector
- # 100-Ohm diff pairs
- DNP
- DNP
- e-con camera 30-pin connector
- OE VCCA
  domain
- R327,R313 - 3.3->1.8 Divider
- R329,R314 - 3.3->1.8 Divider
- # 100-Ohm diff pairs
- DNP
sheet 8
- MIPI-DSI LCD connector
- MIPI LCD touch-panel connector
- # 100-Ohm diff pairs
- # 100-Ohm diff pairs
- Pinout of J5 reversed
   to FPC
- GT911 supports two I2C slave
  addresses: 0xBA/0xBB and 0x28/0x29.
  The host can select the address by
  changing the status of Reset and INT
  pins during the power-on
  initialization phase, refer:
  139D10080 Data Sheet, page 29
- MIPI LCD back-light power
- Typical LED configuration: Two parallel
  chains of 6 serially connected LEDs
- 19.2V/40mA
- DNP
